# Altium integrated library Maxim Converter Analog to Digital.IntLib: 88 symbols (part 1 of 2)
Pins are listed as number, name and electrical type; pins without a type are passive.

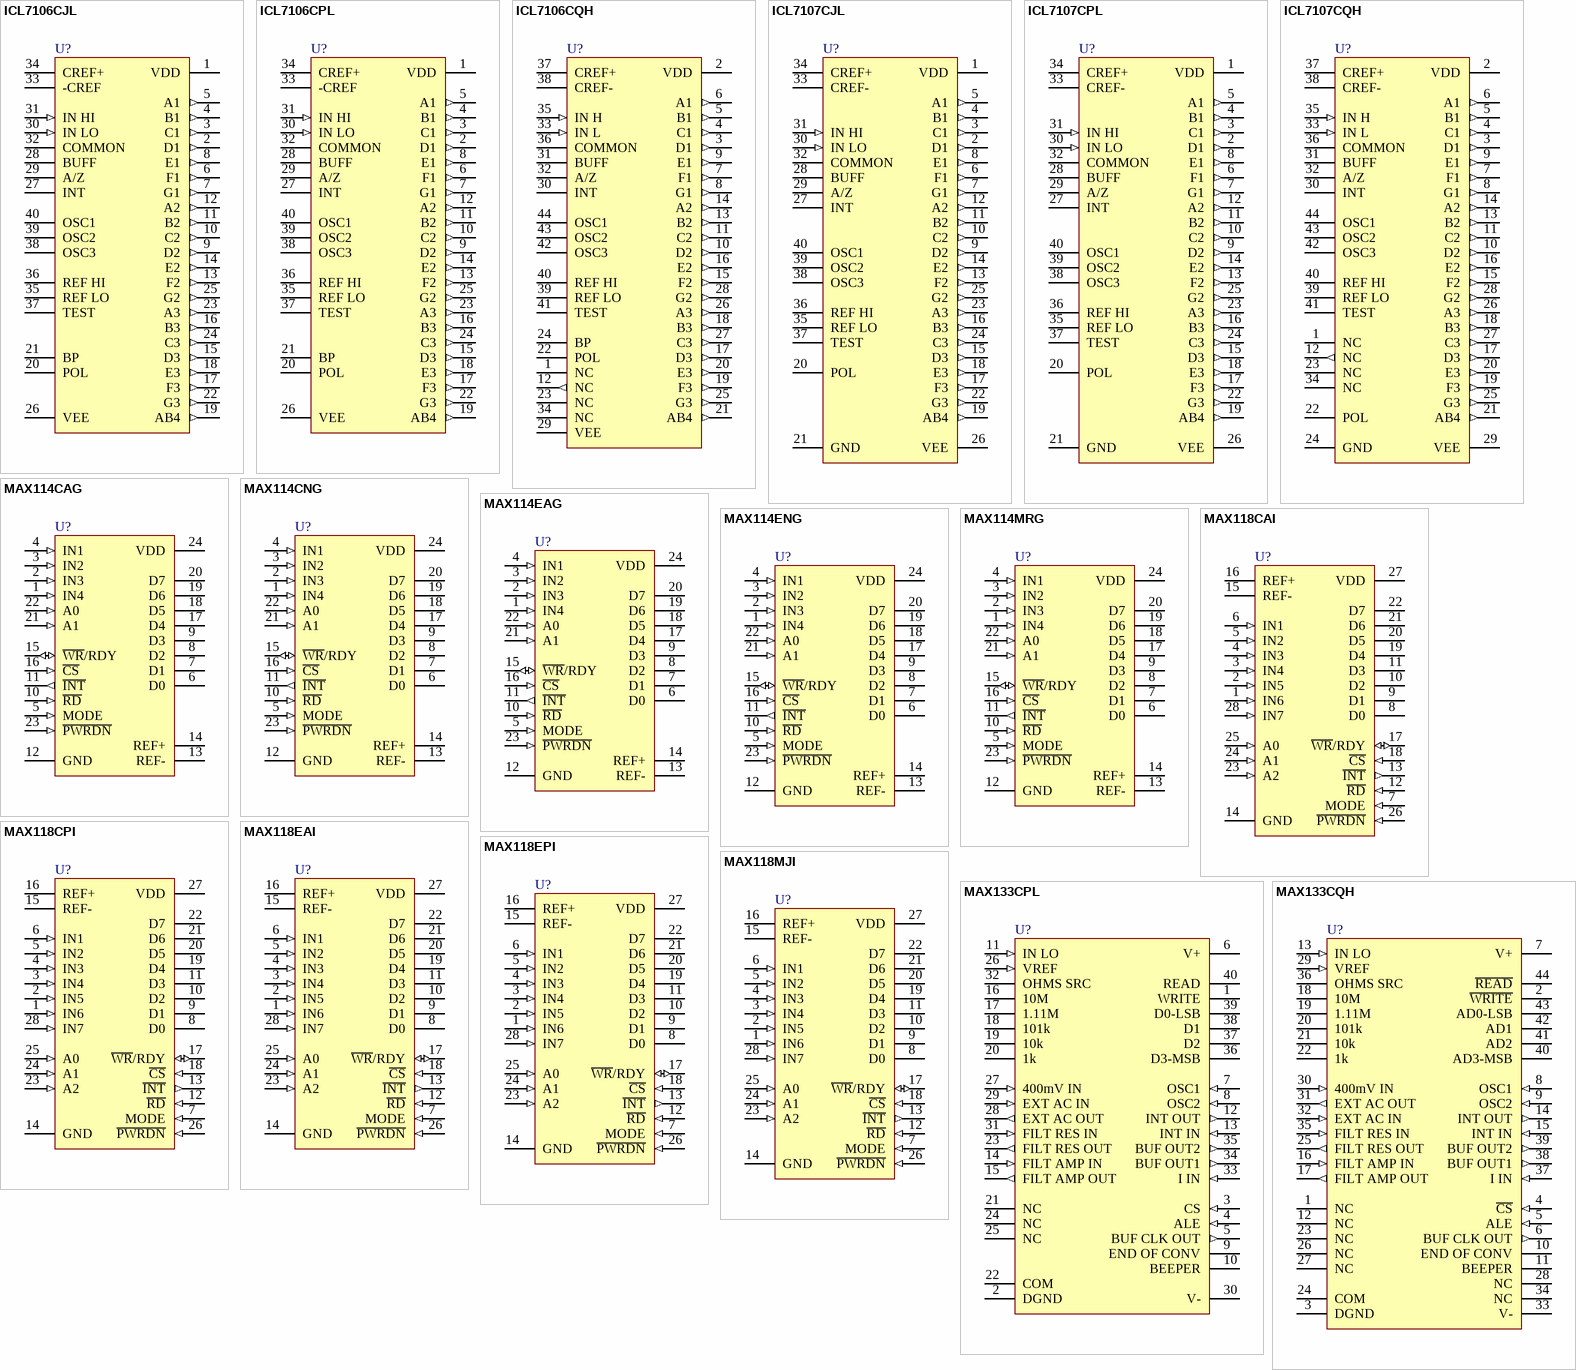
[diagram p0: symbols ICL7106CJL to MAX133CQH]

## ICL7106CJL
designator U?
3½ Digit A/D Converter
footprint JL40A (DIP, 40-Leads, Row Spacing 15.24mm, Pitch 2.54mm, Body 52.28x14.35mm)
3D model JL40A (DIP, 40-Pin, Row Spacing 15.24 mm, Pitch 2.54 mm)
pins: 1 VDD (power), 2 D1 (out), 3 C1 (out), 4 B1 (out), 5 A1 (out), 6 F1 (out), 7 G1 (out), 8 E1 (out), 9 D2 (out), 10 C2 (out), 11 B2 (out), 12 A2 (out), 13 F2 (out), 14 E2 (out), 15 D3 (out), 16 B3 (out), 17 F3 (out), 18 E3 (out), 19 AB4 (out), 20 POL, 21 BP, 22 G3 (out), 23 A3 (out), 24 C3 (out), 25 G2 (out), 26 VEE (power), 27 INT, 28 BUFF, 29 A/Z, 30 IN LO (in), 31 IN HI (in), 32 COMMON, 33 -CREF, 34 CREF+, 35 REF LO, 36 REF HI, 37 TEST, 38 OSC3, 39 OSC2, 40 OSC1

## ICL7106CPL
designator U?
3½ Digit A/D Converter
footprint PL40 (DIP, 40-Leads, Row Spacing 15.24mm, Pitch 2.54mm, Body 52.08x13.98mm)
3D model PL40 (DIP, 40-Pin, Row Spacing 15.24 mm, Pitch 2.54 mm)
pins: 1 VDD (power), 2 D1 (out), 3 C1 (out), 4 B1 (out), 5 A1 (out), 6 F1 (out), 7 G1 (out), 8 E1 (out), 9 D2 (out), 10 C2 (out), 11 B2 (out), 12 A2 (out), 13 F2 (out), 14 E2 (out), 15 D3 (out), 16 B3 (out), 17 F3 (out), 18 E3 (out), 19 AB4 (out), 20 POL, 21 BP, 22 G3 (out), 23 A3 (out), 24 C3 (out), 25 G2 (out), 26 VEE (power), 27 INT, 28 BUFF, 29 A/Z, 30 IN LO (in), 31 IN HI (in), 32 COMMON, 33 -CREF, 34 CREF+, 35 REF LO, 36 REF HI, 37 TEST, 38 OSC3, 39 OSC2, 40 OSC1

## ICL7106CQH
designator U?
3½ Digit A/D Converter
footprint PLCC44_N (Leaded Chip Carrier, 44-Leads, Body 16.6x16.6mm, Pitch 1.27mm, IPC Medium Density)
footprint PLCC44_L (Leaded Chip Carrier, 44-Leads, Body 16.6x16.6mm, Pitch 1.27mm, IPC High Density)
footprint PLCC44_M (Leaded Chip Carrier, 44-Leads, Body 16.6x16.6mm, Pitch 1.27mm, IPC Low Density)
3D model ICL7106-PLCC44 (44-Pin Leaded Chip Carrier 1.27 mm Pitch)
pins: 1 NC, 2 VDD (power), 3 D1 (out), 4 C1 (out), 5 B1 (out), 6 A1 (out), 7 F1 (out), 8 G1 (out), 9 E1 (out), 10 D2 (out), 11 C2 (out), 12 NC (out), 13 B2 (out), 14 A2 (out), 15 F2 (out), 16 E2 (out), 17 D3 (out), 18 B3 (out), 19 F3 (out), 20 E3 (out), 21 AB4 (out), 22 POL, 23 NC, 24 BP, 25 G3 (out), 26 A3 (out), 27 C3 (out), 28 G2 (out), 29 VEE (power), 30 INT, 31 BUFF, 32 A/Z, 33 IN L (in), 34 NC, 35 IN H (in), 36 COMMON, 37 CREF+, 38 CREF-, 39 REF LO, 40 REF HI, 41 TEST, 42 OSC3, 43 OSC2, 44 OSC1

## ICL7107CJL
designator U?
3½ Digit A/D Converter
footprint JL40A (DIP, 40-Leads, Row Spacing 15.24mm, Pitch 2.54mm, Body 52.28x14.35mm)
3D model JL40A (DIP, 40-Pin, Row Spacing 15.24 mm, Pitch 2.54 mm)
pins: 1 VDD (power), 2 D1 (out), 3 C1 (out), 4 B1 (out), 5 A1 (out), 6 F1 (out), 7 G1 (out), 8 E1 (out), 9 D2 (out), 10 C2 (out), 11 B2 (out), 12 A2 (out), 13 F2 (out), 14 E2 (out), 15 D3 (out), 16 B3 (out), 17 F3 (out), 18 E3 (out), 19 AB4 (out), 20 POL, 21 GND (power), 22 G3 (out), 23 A3 (out), 24 C3 (out), 25 G2 (out), 26 VEE (power), 27 INT, 28 BUFF, 29 A/Z, 30 IN LO (in), 31 IN HI (in), 32 COMMON, 33 CREF-, 34 CREF+, 35 REF LO, 36 REF HI, 37 TEST, 38 OSC3, 39 OSC2, 40 OSC1

## ICL7107CPL
designator U?
3½ Digit A/D Converter
footprint PL40 (DIP, 40-Leads, Row Spacing 15.24mm, Pitch 2.54mm, Body 52.08x13.98mm)
3D model PL40 (DIP, 40-Pin, Row Spacing 15.24 mm, Pitch 2.54 mm)
pins: 1 VDD (power), 2 D1 (out), 3 C1 (out), 4 B1 (out), 5 A1 (out), 6 F1 (out), 7 G1 (out), 8 E1 (out), 9 D2 (out), 10 C2 (out), 11 B2 (out), 12 A2 (out), 13 F2 (out), 14 E2 (out), 15 D3 (out), 16 B3 (out), 17 F3 (out), 18 E3 (out), 19 AB4 (out), 20 POL, 21 GND (power), 22 G3 (out), 23 A3 (out), 24 C3 (out), 25 G2 (out), 26 VEE (power), 27 INT, 28 BUFF, 29 A/Z, 30 IN LO (in), 31 IN HI (in), 32 COMMON, 33 CREF-, 34 CREF+, 35 REF LO, 36 REF HI, 37 TEST, 38 OSC3, 39 OSC2, 40 OSC1

## ICL7107CQH
designator U?
3½ Digit A/D Converter
footprint PLCC44_N (Leaded Chip Carrier, 44-Leads, Body 16.6x16.6mm, Pitch 1.27mm, IPC Medium Density)
footprint PLCC44_L (Leaded Chip Carrier, 44-Leads, Body 16.6x16.6mm, Pitch 1.27mm, IPC High Density)
footprint PLCC44_M (Leaded Chip Carrier, 44-Leads, Body 16.6x16.6mm, Pitch 1.27mm, IPC Low Density)
3D model ICL7107-PLCC44 (44-Pin Leaded Chip Carrier 1.27 mm Pitch)
pins: 1 NC, 2 VDD (power), 3 D1 (out), 4 C1 (out), 5 B1 (out), 6 A1 (out), 7 F1 (out), 8 G1 (out), 9 E1 (out), 10 D2 (out), 11 C2 (out), 12 NC (out), 13 B2 (out), 14 A2 (out), 15 F2 (out), 16 E2 (out), 17 D3 (out), 18 B3 (out), 19 F3 (out), 20 E3 (out), 21 AB4 (out), 22 POL, 23 NC, 24 GND (power), 25 G3 (out), 26 A3 (out), 27 C3 (out), 28 G2 (out), 29 VEE (power), 30 INT, 31 BUFF, 32 A/Z, 33 IN L (in), 34 NC, 35 IN H (in), 36 COMMON, 37 CREF+, 38 CREF-, 39 REF LO, 40 REF HI, 41 TEST, 42 OSC3, 43 OSC2, 44 OSC1

## MAX114CAG
designator U?
+5V, 1Msps, 4-Channel, 8-Bit ADCs with 1µA Power-Down
footprint SSOP24_N (SOP, 24-Leads, Body 8.2x5.3mm, Pitch 0.65mm, IPC Medium Density)
footprint SSOP24_L (SOP, 24-Leads, Body 8.2x5.3mm, Pitch 0.65mm, IPC High Density)
footprint SSOP24_M (SOP, 24-Leads, Body 8.2x5.3mm, Pitch 0.65mm, IPC Low Density)
3D model SSOP24 (24-Pin Small Outline Package 0.65 mm Pitch)
pins: 1 IN4 (in), 2 IN3 (in), 3 IN2 (in), 4 IN1 (in), 5 MODE (in), 6 D0 (hiz), 7 D1 (hiz), 8 D2 (hiz), 9 D3 (hiz), 10 ~{RD} (in), 11 ~{INT} (out), 12 GND (power), 13 REF-, 14 REF+, 15 ~{WR}/RDY (io), 16 ~{CS} (in), 17 D4 (hiz), 18 D5 (hiz), 19 D6 (hiz), 20 D7 (hiz), 21 A1 (in), 22 A0 (in), 23 ~{PWRDN} (in), 24 VDD (power)

## MAX114CNG
designator U?
+5V, 1Msps, 4-Channel, 8-Bit ADCs with 1µA Power-Down
footprint NG24 (DIP, 24-Leads, Row Spacing 7.62mm, Pitch 2.54mm, Body 30.55x7.24mm)
3D model NG24 (DIP, 24-Pin, Row Spacing 7.62 mm, Pitch 2.54 mm)
pins: 1 IN4 (in), 2 IN3 (in), 3 IN2 (in), 4 IN1 (in), 5 MODE (in), 6 D0 (hiz), 7 D1 (hiz), 8 D2 (hiz), 9 D3 (hiz), 10 ~{RD} (in), 11 ~{INT} (out), 12 GND (power), 13 REF-, 14 REF+, 15 ~{WR}/RDY (io), 16 ~{CS} (in), 17 D4 (hiz), 18 D5 (hiz), 19 D6 (hiz), 20 D7 (hiz), 21 A1 (in), 22 A0 (in), 23 ~{PWRDN} (in), 24 VDD (power)

## MAX114EAG
designator U?
+5V, 1Msps, 4-Channel, 8-Bit ADCs with 1µA Power-Down
footprint SSOP24_N (SOP, 24-Leads, Body 8.2x5.3mm, Pitch 0.65mm, IPC Medium Density)
footprint SSOP24_L (SOP, 24-Leads, Body 8.2x5.3mm, Pitch 0.65mm, IPC High Density)
footprint SSOP24_M (SOP, 24-Leads, Body 8.2x5.3mm, Pitch 0.65mm, IPC Low Density)
3D model SSOP24 (24-Pin Small Outline Package 0.65 mm Pitch)
pins: 1 IN4 (in), 2 IN3 (in), 3 IN2 (in), 4 IN1 (in), 5 MODE (in), 6 D0 (hiz), 7 D1 (hiz), 8 D2 (hiz), 9 D3 (hiz), 10 ~{RD} (in), 11 ~{INT} (out), 12 GND (power), 13 REF-, 14 REF+, 15 ~{WR}/RDY (io), 16 ~{CS} (in), 17 D4 (hiz), 18 D5 (hiz), 19 D6 (hiz), 20 D7 (hiz), 21 A1 (in), 22 A0 (in), 23 ~{PWRDN} (in), 24 VDD (power)

## MAX114ENG
designator U?
+5V, 1Msps, 4-Channel, 8-Bit ADCs with 1µA Power-Down
footprint NG24 (DIP, 24-Leads, Row Spacing 7.62mm, Pitch 2.54mm, Body 30.55x7.24mm)
3D model NG24 (DIP, 24-Pin, Row Spacing 7.62 mm, Pitch 2.54 mm)
pins: 1 IN4 (in), 2 IN3 (in), 3 IN2 (in), 4 IN1 (in), 5 MODE (in), 6 D0 (hiz), 7 D1 (hiz), 8 D2 (hiz), 9 D3 (hiz), 10 ~{RD} (in), 11 ~{INT} (out), 12 GND (power), 13 REF-, 14 REF+, 15 ~{WR}/RDY (io), 16 ~{CS} (in), 17 D4 (hiz), 18 D5 (hiz), 19 D6 (hiz), 20 D7 (hiz), 21 A1 (in), 22 A0 (in), 23 ~{PWRDN} (in), 24 VDD (power)

## MAX114MRG
designator U?
+5V, 1Msps, 4-Channel, 8-Bit ADCs with 1µA Power-Down
footprint RG24 (DIP, 24-Leads, Row Spacing 7.62mm, Pitch 2.54mm, Body 31.88x6.73mm)
3D model NG24 (DIP, 24-Pin, Row Spacing 7.62 mm, Pitch 2.54 mm)
pins: 1 IN4 (in), 2 IN3 (in), 3 IN2 (in), 4 IN1 (in), 5 MODE (in), 6 D0 (hiz), 7 D1 (hiz), 8 D2 (hiz), 9 D3 (hiz), 10 ~{RD} (in), 11 ~{INT} (out), 12 GND (power), 13 REF-, 14 REF+, 15 ~{WR}/RDY (io), 16 ~{CS} (in), 17 D4 (hiz), 18 D5 (hiz), 19 D6 (hiz), 20 D7 (hiz), 21 A1 (in), 22 A0 (in), 23 ~{PWRDN} (in), 24 VDD (power)

## MAX118CAI
designator U?
+5V, 1Msps, 8-Channel, 8-Bit ADCs with 1µA Power-Down
footprint SSOP28_N (SOP, 28-Leads, Body 10.2x5.3mm, Pitch 0.65mm, IPC Medium Density)
footprint SSOP28_L (SOP, 28-Leads, Body 10.2x5.3mm, Pitch 0.65mm, IPC High Density)
footprint SSOP28_M (SOP, 28-Leads, Body 10.2x5.3mm, Pitch 0.65mm, IPC Low Density)
3D model SSOP28 (28-Pin Small Outline Package 0.65 mm Pitch)
pins: 1 IN6 (in), 2 IN5 (in), 3 IN4 (in), 4 IN3 (in), 5 IN2 (in), 6 IN1 (in), 7 MODE (in), 8 D0 (hiz), 9 D1 (hiz), 10 D2 (hiz), 11 D3 (hiz), 12 ~{RD} (in), 13 ~{INT} (out), 14 GND (power), 15 REF-, 16 REF+, 17 ~{WR}/RDY (io), 18 ~{CS} (in), 19 D4 (hiz), 20 D5 (hiz), 21 D6 (hiz), 22 D7 (hiz), 23 A2 (in), 24 A1 (in), 25 A0 (in), 26 ~{PWRDN} (in), 27 VDD (power), 28 IN7 (in)

## MAX118CPI
designator U?
+5V, 1Msps, 8-Channel, 8-Bit ADCs with 1µA Power-Down
footprint PI28 (DIP, 28-Leads, Row Spacing 15.24mm, Pitch 2.54mm, Body 36.83x13.98mm)
3D model JI28 (DIP, 28-Pin, Row Spacing 15.24 mm, Pitch 2.54 mm)
pins: 1 IN6 (in), 2 IN5 (in), 3 IN4 (in), 4 IN3 (in), 5 IN2 (in), 6 IN1 (in), 7 MODE (in), 8 D0 (hiz), 9 D1 (hiz), 10 D2 (hiz), 11 D3 (hiz), 12 ~{RD} (in), 13 ~{INT} (out), 14 GND (power), 15 REF-, 16 REF+, 17 ~{WR}/RDY (io), 18 ~{CS} (in), 19 D4 (hiz), 20 D5 (hiz), 21 D6 (hiz), 22 D7 (hiz), 23 A2 (in), 24 A1 (in), 25 A0 (in), 26 ~{PWRDN} (in), 27 VDD (power), 28 IN7 (in)

## MAX118EAI
designator U?
+5V, 1Msps, 8-Channel, 8-Bit ADCs with 1µA Power-Down
footprint SSOP28_N (SOP, 28-Leads, Body 10.2x5.3mm, Pitch 0.65mm, IPC Medium Density)
footprint SSOP28_L (SOP, 28-Leads, Body 10.2x5.3mm, Pitch 0.65mm, IPC High Density)
footprint SSOP28_M (SOP, 28-Leads, Body 10.2x5.3mm, Pitch 0.65mm, IPC Low Density)
3D model SSOP28 (28-Pin Small Outline Package 0.65 mm Pitch)
pins: 1 IN6 (in), 2 IN5 (in), 3 IN4 (in), 4 IN3 (in), 5 IN2 (in), 6 IN1 (in), 7 MODE (in), 8 D0 (hiz), 9 D1 (hiz), 10 D2 (hiz), 11 D3 (hiz), 12 ~{RD} (in), 13 ~{INT} (out), 14 GND (power), 15 REF-, 16 REF+, 17 ~{WR}/RDY (io), 18 ~{CS} (in), 19 D4 (hiz), 20 D5 (hiz), 21 D6 (hiz), 22 D7 (hiz), 23 A2 (in), 24 A1 (in), 25 A0 (in), 26 ~{PWRDN} (in), 27 VDD (power), 28 IN7 (in)

## MAX118EPI
designator U?
+5V, 1Msps, 8-Channel, 8-Bit ADCs with 1µA Power-Down
footprint PI28 (DIP, 28-Leads, Row Spacing 15.24mm, Pitch 2.54mm, Body 36.83x13.98mm)
3D model JI28 (DIP, 28-Pin, Row Spacing 15.24 mm, Pitch 2.54 mm)
pins: 1 IN6 (in), 2 IN5 (in), 3 IN4 (in), 4 IN3 (in), 5 IN2 (in), 6 IN1 (in), 7 MODE (in), 8 D0 (hiz), 9 D1 (hiz), 10 D2 (hiz), 11 D3 (hiz), 12 ~{RD} (in), 13 ~{INT} (out), 14 GND (power), 15 REF-, 16 REF+, 17 ~{WR}/RDY (io), 18 ~{CS} (in), 19 D4 (hiz), 20 D5 (hiz), 21 D6 (hiz), 22 D7 (hiz), 23 A2 (in), 24 A1 (in), 25 A0 (in), 26 ~{PWRDN} (in), 27 VDD (power), 28 IN7 (in)

## MAX118MJI
designator U?
+5V, 1Msps, 8-Channel, 8-Bit ADCs with 1µA Power-Down
footprint JI28 (DIP, 28-Leads, Row Spacing 15.24mm, Pitch 2.54mm, Body 37.15x14.23mm)
3D model JI28 (DIP, 28-Pin, Row Spacing 15.24 mm, Pitch 2.54 mm)
pins: 1 IN6 (in), 2 IN5 (in), 3 IN4 (in), 4 IN3 (in), 5 IN2 (in), 6 IN1 (in), 7 MODE (in), 8 D0 (hiz), 9 D1 (hiz), 10 D2 (hiz), 11 D3 (hiz), 12 ~{RD} (in), 13 ~{INT} (out), 14 GND (power), 15 REF-, 16 REF+, 17 ~{WR}/RDY (io), 18 ~{CS} (in), 19 D4 (hiz), 20 D5 (hiz), 21 D6 (hiz), 22 D7 (hiz), 23 A2 (in), 24 A1 (in), 25 A0 (in), 26 ~{PWRDN} (in), 27 VDD (power), 28 IN7 (in)

## MAX133CPL
designator U?
3¾ Digit DMM Circuit
footprint PL40 (DIP, 40-Leads, Row Spacing 15.24mm, Pitch 2.54mm, Body 52.08x13.98mm)
3D model PL40 (DIP, 40-Pin, Row Spacing 15.24 mm, Pitch 2.54 mm)
pins: 1 WRITE, 2 DGND (power), 3 CS (in), 4 ALE (in), 5 BUF CLK OUT (out), 6 V+ (power), 7 OSC1 (in), 8 OSC2 (in), 9 END OF CONV, 10 BEEPER, 11 IN LO (in), 12 INT OUT (out), 13 INT IN (in), 14 FILT AMP IN (in), 15 FILT AMP OUT (out), 16 10M, 17 1.11M, 18 101k, 19 10k, 20 1k, 21 NC, 22 COM (power), 23 FILT RES OUT (out), 24 NC, 25 NC, 26 VREF (in), 27 400mV IN (in), 28 EXT AC OUT (out), 29 EXT AC IN (in), 30 V- (power), 31 FILT RES IN (in), 32 OHMS SRC, 33 I IN (in), 34 BUF OUT1 (out), 35 BUF OUT2 (out), 36 D3-MSB, 37 D2, 38 D1, 39 D0-LSB, 40 READ

## MAX133CQH
designator U?
3¾ Digit DMM Circuit
footprint PLCC44_N (Leaded Chip Carrier, 44-Leads, Body 16.6x16.6mm, Pitch 1.27mm, IPC Medium Density)
footprint PLCC44_L (Leaded Chip Carrier, 44-Leads, Body 16.6x16.6mm, Pitch 1.27mm, IPC High Density)
footprint PLCC44_M (Leaded Chip Carrier, 44-Leads, Body 16.6x16.6mm, Pitch 1.27mm, IPC Low Density)
3D model MAX133-PLCC44 (44-Pin Leaded Chip Carrier 1.27 mm Pitch)
pins: 1 NC, 2 ~{WRITE}, 3 DGND (power), 4 ~{CS} (in), 5 ALE (in), 6 BUF CLK OUT (out), 7 V+ (power), 8 OSC1 (in), 9 OSC2 (in), 10 END OF CONV, 11 BEEPER, 12 NC, 13 IN LO (in), 14 INT OUT (out), 15 INT IN (in), 16 FILT AMP IN (in), 17 FILT AMP OUT (out), 18 10M, 19 1.11M, 20 101k, 21 10k, 22 1k, 23 NC, 24 COM (power), 25 FILT RES OUT (out), 26 NC, 27 NC, 28 NC, 29 VREF (in), 30 400mV IN (in), 31 EXT AC OUT (out), 32 EXT AC IN (in), 33 V- (power), 34 NC, 35 FILT RES IN (in), 36 OHMS SRC, 37 I IN (in), 38 BUF OUT1 (out), 39 BUF OUT2 (out), 40 AD3-MSB, 41 AD2, 42 AD1, 43 AD0-LSB, 44 ~{READ}

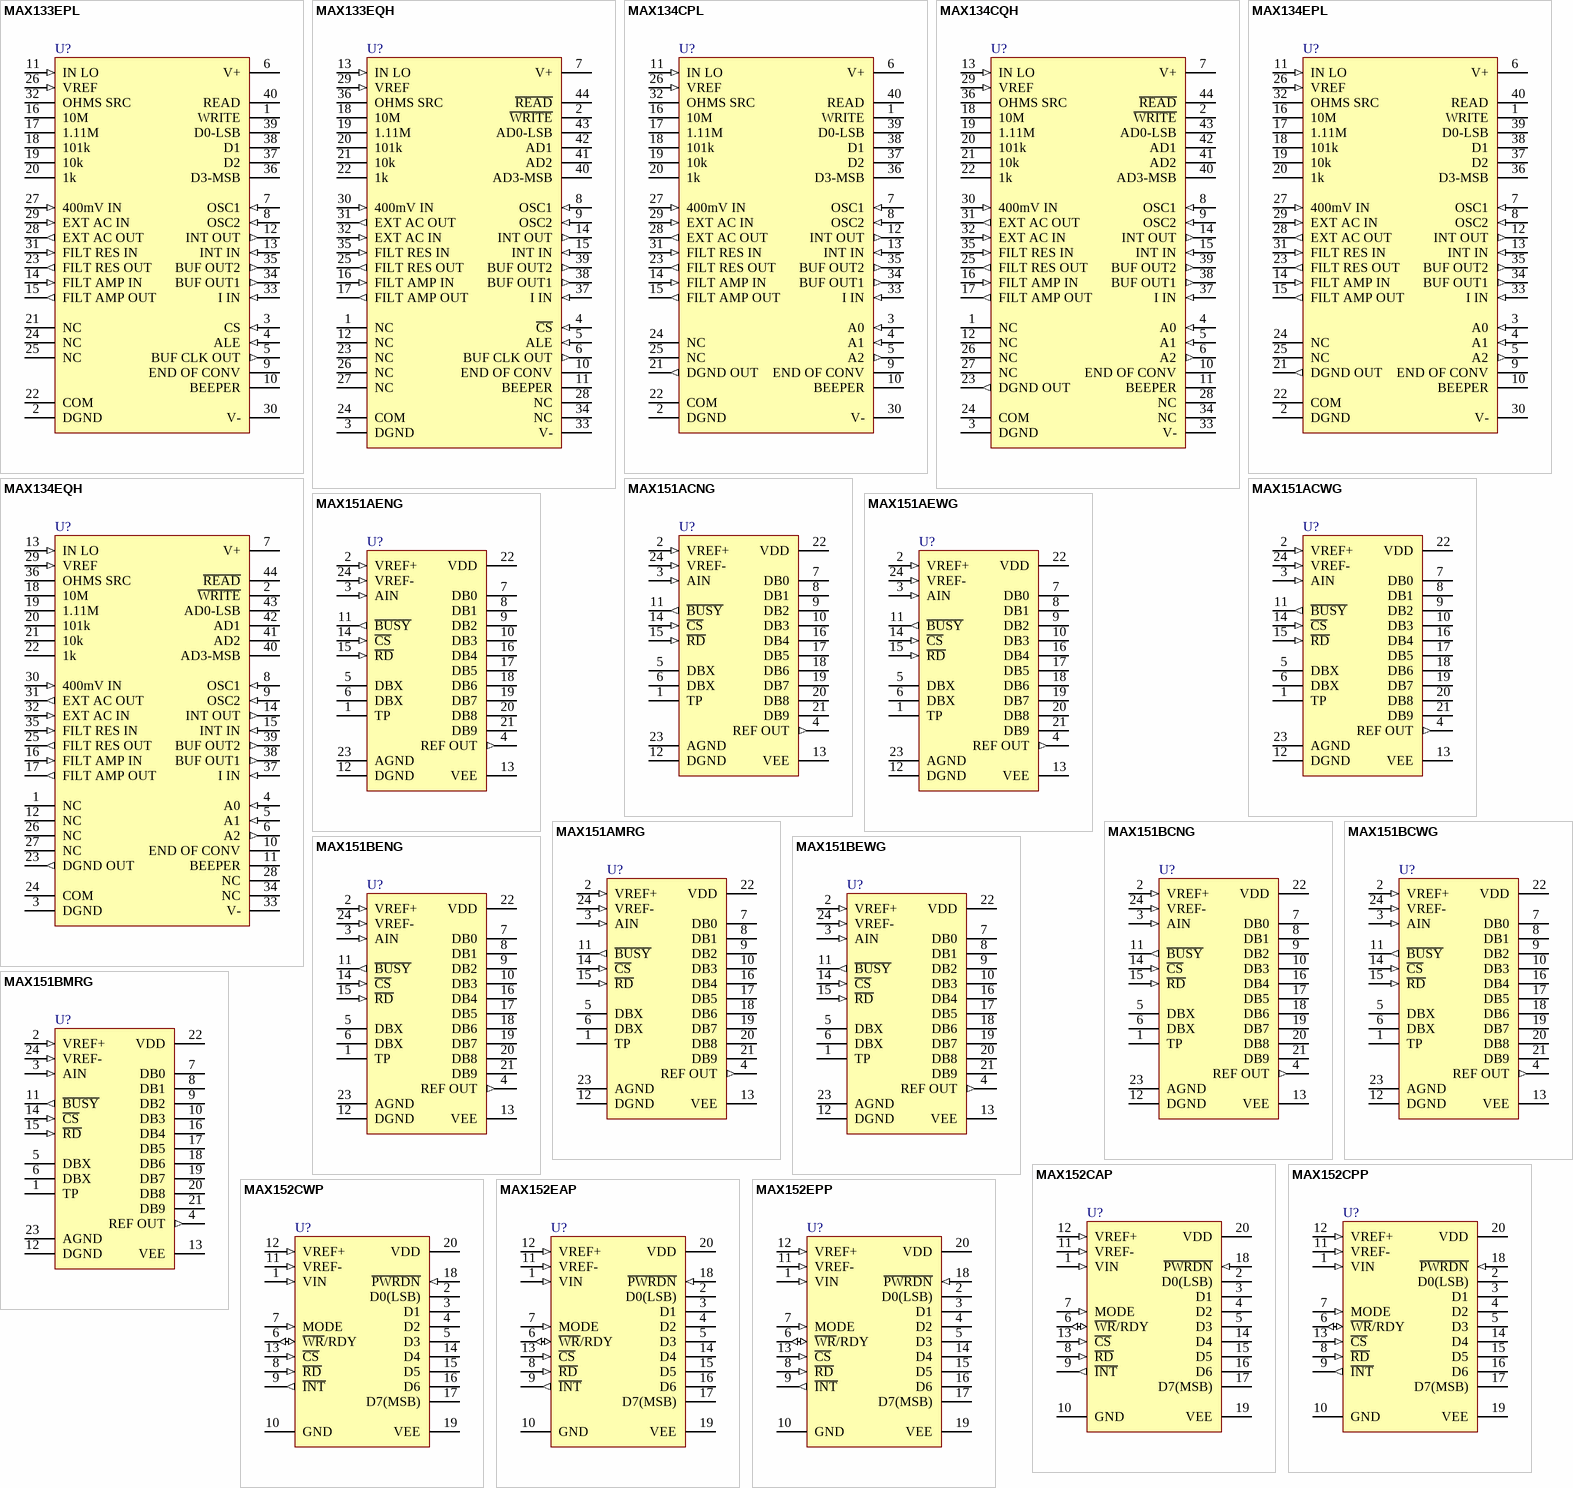
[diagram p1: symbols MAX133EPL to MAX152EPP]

## MAX133EPL
designator U?
3¾ Digit DMM Circuit
footprint PL40 (DIP, 40-Leads, Row Spacing 15.24mm, Pitch 2.54mm, Body 52.08x13.98mm)
3D model PL40 (DIP, 40-Pin, Row Spacing 15.24 mm, Pitch 2.54 mm)
pins: 1 WRITE, 2 DGND (power), 3 CS (in), 4 ALE (in), 5 BUF CLK OUT (out), 6 V+ (power), 7 OSC1 (in), 8 OSC2 (in), 9 END OF CONV, 10 BEEPER, 11 IN LO (in), 12 INT OUT (out), 13 INT IN (in), 14 FILT AMP IN (in), 15 FILT AMP OUT (out), 16 10M, 17 1.11M, 18 101k, 19 10k, 20 1k, 21 NC, 22 COM (power), 23 FILT RES OUT (out), 24 NC, 25 NC, 26 VREF (in), 27 400mV IN (in), 28 EXT AC OUT (out), 29 EXT AC IN (in), 30 V- (power), 31 FILT RES IN (in), 32 OHMS SRC, 33 I IN (in), 34 BUF OUT1 (out), 35 BUF OUT2 (out), 36 D3-MSB, 37 D2, 38 D1, 39 D0-LSB, 40 READ

## MAX133EQH
designator U?
3¾ Digit DMM Circuit
footprint PLCC44_N (Leaded Chip Carrier, 44-Leads, Body 16.6x16.6mm, Pitch 1.27mm, IPC Medium Density)
footprint PLCC44_L (Leaded Chip Carrier, 44-Leads, Body 16.6x16.6mm, Pitch 1.27mm, IPC High Density)
footprint PLCC44_M (Leaded Chip Carrier, 44-Leads, Body 16.6x16.6mm, Pitch 1.27mm, IPC Low Density)
3D model MAX133-PLCC44 (44-Pin Leaded Chip Carrier 1.27 mm Pitch)
pins: 1 NC, 2 ~{WRITE}, 3 DGND (power), 4 ~{CS} (in), 5 ALE (in), 6 BUF CLK OUT (out), 7 V+ (power), 8 OSC1 (in), 9 OSC2 (in), 10 END OF CONV, 11 BEEPER, 12 NC, 13 IN LO (in), 14 INT OUT (out), 15 INT IN (in), 16 FILT AMP IN (in), 17 FILT AMP OUT (out), 18 10M, 19 1.11M, 20 101k, 21 10k, 22 1k, 23 NC, 24 COM (power), 25 FILT RES OUT (out), 26 NC, 27 NC, 28 NC, 29 VREF (in), 30 400mV IN (in), 31 EXT AC OUT (out), 32 EXT AC IN (in), 33 V- (power), 34 NC, 35 FILT RES IN (in), 36 OHMS SRC, 37 I IN (in), 38 BUF OUT1 (out), 39 BUF OUT2 (out), 40 AD3-MSB, 41 AD2, 42 AD1, 43 AD0-LSB, 44 ~{READ}

## MAX134CPL
designator U?
3¾ Digit DMM Circuit
footprint PL40 (DIP, 40-Leads, Row Spacing 15.24mm, Pitch 2.54mm, Body 52.08x13.98mm)
3D model PL40 (DIP, 40-Pin, Row Spacing 15.24 mm, Pitch 2.54 mm)
pins: 1 WRITE, 2 DGND (power), 3 A0 (in), 4 A1 (in), 5 A2 (out), 6 V+ (power), 7 OSC1 (in), 8 OSC2 (in), 9 END OF CONV, 10 BEEPER, 11 IN LO (in), 12 INT OUT (out), 13 INT IN (in), 14 FILT AMP IN (in), 15 FILT AMP OUT (out), 16 10M, 17 1.11M, 18 101k, 19 10k, 20 1k, 21 DGND OUT (out), 22 COM (power), 23 FILT RES OUT (out), 24 NC, 25 NC, 26 VREF (in), 27 400mV IN (in), 28 EXT AC OUT (out), 29 EXT AC IN (in), 30 V- (power), 31 FILT RES IN (in), 32 OHMS SRC, 33 I IN (in), 34 BUF OUT1 (out), 35 BUF OUT2 (out), 36 D3-MSB, 37 D2, 38 D1, 39 D0-LSB, 40 READ

## MAX134CQH
designator U?
3¾ Digit DMM Circuit
footprint PLCC44_N (Leaded Chip Carrier, 44-Leads, Body 16.6x16.6mm, Pitch 1.27mm, IPC Medium Density)
footprint PLCC44_L (Leaded Chip Carrier, 44-Leads, Body 16.6x16.6mm, Pitch 1.27mm, IPC High Density)
footprint PLCC44_M (Leaded Chip Carrier, 44-Leads, Body 16.6x16.6mm, Pitch 1.27mm, IPC Low Density)
3D model MAX134-PLCC44 (44-Pin Leaded Chip Carrier 1.27 mm Pitch)
pins: 1 NC, 2 ~{WRITE}, 3 DGND (power), 4 A0 (in), 5 A1 (in), 6 A2 (out), 7 V+ (power), 8 OSC1 (in), 9 OSC2 (in), 10 END OF CONV, 11 BEEPER, 12 NC, 13 IN LO (in), 14 INT OUT (out), 15 INT IN (in), 16 FILT AMP IN (in), 17 FILT AMP OUT (out), 18 10M, 19 1.11M, 20 101k, 21 10k, 22 1k, 23 DGND OUT (out), 24 COM (power), 25 FILT RES OUT (out), 26 NC, 27 NC, 28 NC, 29 VREF (in), 30 400mV IN (in), 31 EXT AC OUT (out), 32 EXT AC IN (in), 33 V- (power), 34 NC, 35 FILT RES IN (in), 36 OHMS SRC, 37 I IN (in), 38 BUF OUT1 (out), 39 BUF OUT2 (out), 40 AD3-MSB, 41 AD2, 42 AD1, 43 AD0-LSB, 44 ~{READ}

## MAX134EPL
designator U?
3¾ Digit DMM Circuit
footprint PL40 (DIP, 40-Leads, Row Spacing 15.24mm, Pitch 2.54mm, Body 52.08x13.98mm)
3D model PL40 (DIP, 40-Pin, Row Spacing 15.24 mm, Pitch 2.54 mm)
pins: 1 WRITE, 2 DGND (power), 3 A0 (in), 4 A1 (in), 5 A2 (out), 6 V+ (power), 7 OSC1 (in), 8 OSC2 (in), 9 END OF CONV, 10 BEEPER, 11 IN LO (in), 12 INT OUT (out), 13 INT IN (in), 14 FILT AMP IN (in), 15 FILT AMP OUT (out), 16 10M, 17 1.11M, 18 101k, 19 10k, 20 1k, 21 DGND OUT (out), 22 COM (power), 23 FILT RES OUT (out), 24 NC, 25 NC, 26 VREF (in), 27 400mV IN (in), 28 EXT AC OUT (out), 29 EXT AC IN (in), 30 V- (power), 31 FILT RES IN (in), 32 OHMS SRC, 33 I IN (in), 34 BUF OUT1 (out), 35 BUF OUT2 (out), 36 D3-MSB, 37 D2, 38 D1, 39 D0-LSB, 40 READ

## MAX134EQH
designator U?
3¾ Digit DMM Circuit
footprint PLCC44_N (Leaded Chip Carrier, 44-Leads, Body 16.6x16.6mm, Pitch 1.27mm, IPC Medium Density)
footprint PLCC44_L (Leaded Chip Carrier, 44-Leads, Body 16.6x16.6mm, Pitch 1.27mm, IPC High Density)
footprint PLCC44_M (Leaded Chip Carrier, 44-Leads, Body 16.6x16.6mm, Pitch 1.27mm, IPC Low Density)
3D model MAX134-PLCC44 (44-Pin Leaded Chip Carrier 1.27 mm Pitch)
pins: 1 NC, 2 ~{WRITE}, 3 DGND (power), 4 A0 (in), 5 A1 (in), 6 A2 (out), 7 V+ (power), 8 OSC1 (in), 9 OSC2 (in), 10 END OF CONV, 11 BEEPER, 12 NC, 13 IN LO (in), 14 INT OUT (out), 15 INT IN (in), 16 FILT AMP IN (in), 17 FILT AMP OUT (out), 18 10M, 19 1.11M, 20 101k, 21 10k, 22 1k, 23 DGND OUT (out), 24 COM (power), 25 FILT RES OUT (out), 26 NC, 27 NC, 28 NC, 29 VREF (in), 30 400mV IN (in), 31 EXT AC OUT (out), 32 EXT AC IN (in), 33 V- (power), 34 NC, 35 FILT RES IN (in), 36 OHMS SRC, 37 I IN (in), 38 BUF OUT1 (out), 39 BUF OUT2 (out), 40 AD3-MSB, 41 AD2, 42 AD1, 43 AD0-LSB, 44 ~{READ}

## MAX151ACNG
designator U?
300kHz 10-Bit ADC Converter with Reference and T/H
footprint NG24A (DIP, 24-Leads, Row Spacing 7.62mm, Pitch 2.54mm, Body 30.55x6.99mm)
3D model NG24 (DIP, 24-Pin, Row Spacing 7.62 mm, Pitch 2.54 mm)
pins: 1 TP, 2 VREF+ (in), 3 AIN (in), 4 REF OUT (out), 5 DBX, 6 DBX, 7 DB0 (hiz), 8 DB1 (hiz), 9 DB2 (hiz), 10 DB3 (hiz), 11 ~{BUSY} (out), 12 DGND (power), 13 VEE (power), 14 ~{CS} (in), 15 ~{RD} (in), 16 DB4 (hiz), 17 DB5 (hiz), 18 DB6 (hiz), 19 DB7 (hiz), 20 DB8 (hiz), 21 DB9 (hiz), 22 VDD (power), 23 AGND (power), 24 VREF- (in)

## MAX151ACWG
designator U?
300kHz 10-Bit ADC Converter with Reference and T/H
footprint WSO24_N (SOIC, 24-Leads, Body 15.4x7.5mm, Pitch 1.27mm, IPC Medium Density)
footprint WSO24_L (SOIC, 24-Leads, Body 15.4x7.5mm, Pitch 1.27mm, IPC High Density)
footprint WSO24_M (SOIC, 24-Leads, Body 15.4x7.5mm, Pitch 1.27mm, IPC Low Density)
3D model WSO24 (24-Pin Small Outline Integrated Circuit 1.27 mm Pitch)
pins: 1 TP, 2 VREF+ (in), 3 AIN (in), 4 REF OUT (out), 5 DBX, 6 DBX, 7 DB0 (hiz), 8 DB1 (hiz), 9 DB2 (hiz), 10 DB3 (hiz), 11 ~{BUSY} (out), 12 DGND (power), 13 VEE (power), 14 ~{CS} (in), 15 ~{RD} (in), 16 DB4 (hiz), 17 DB5 (hiz), 18 DB6 (hiz), 19 DB7 (hiz), 20 DB8 (hiz), 21 DB9 (hiz), 22 VDD (power), 23 AGND (power), 24 VREF- (in)

## MAX151AENG
designator U?
300kHz 10-Bit ADC Converter with Reference and T/H
footprint NG24A (DIP, 24-Leads, Row Spacing 7.62mm, Pitch 2.54mm, Body 30.55x6.99mm)
3D model NG24 (DIP, 24-Pin, Row Spacing 7.62 mm, Pitch 2.54 mm)
pins: 1 TP, 2 VREF+ (in), 3 AIN (in), 4 REF OUT (out), 5 DBX, 6 DBX, 7 DB0 (hiz), 8 DB1 (hiz), 9 DB2 (hiz), 10 DB3 (hiz), 11 ~{BUSY} (out), 12 DGND (power), 13 VEE (power), 14 ~{CS} (in), 15 ~{RD} (in), 16 DB4 (hiz), 17 DB5 (hiz), 18 DB6 (hiz), 19 DB7 (hiz), 20 DB8 (hiz), 21 DB9 (hiz), 22 VDD (power), 23 AGND (power), 24 VREF- (in)

## MAX151AEWG
designator U?
300kHz 10-Bit ADC Converter with Reference and T/H
footprint WSO24_N (SOIC, 24-Leads, Body 15.4x7.5mm, Pitch 1.27mm, IPC Medium Density)
footprint WSO24_L (SOIC, 24-Leads, Body 15.4x7.5mm, Pitch 1.27mm, IPC High Density)
footprint WSO24_M (SOIC, 24-Leads, Body 15.4x7.5mm, Pitch 1.27mm, IPC Low Density)
3D model WSO24 (24-Pin Small Outline Integrated Circuit 1.27 mm Pitch)
pins: 1 TP, 2 VREF+ (in), 3 AIN (in), 4 REF OUT (out), 5 DBX, 6 DBX, 7 DB0 (hiz), 8 DB1 (hiz), 9 DB2 (hiz), 10 DB3 (hiz), 11 ~{BUSY} (out), 12 DGND (power), 13 VEE (power), 14 ~{CS} (in), 15 ~{RD} (in), 16 DB4 (hiz), 17 DB5 (hiz), 18 DB6 (hiz), 19 DB7 (hiz), 20 DB8 (hiz), 21 DB9 (hiz), 22 VDD (power), 23 AGND (power), 24 VREF- (in)

## MAX151AMRG
designator U?
300kHz 10-Bit ADC Converter with Reference and T/H
footprint RG24 (DIP, 24-Leads, Row Spacing 7.62mm, Pitch 2.54mm, Body 31.88x6.73mm)
3D model NG24 (DIP, 24-Pin, Row Spacing 7.62 mm, Pitch 2.54 mm)
pins: 1 TP, 2 VREF+ (in), 3 AIN (in), 4 REF OUT (out), 5 DBX, 6 DBX, 7 DB0 (hiz), 8 DB1 (hiz), 9 DB2 (hiz), 10 DB3 (hiz), 11 ~{BUSY} (out), 12 DGND (power), 13 VEE (power), 14 ~{CS} (in), 15 ~{RD} (in), 16 DB4 (hiz), 17 DB5 (hiz), 18 DB6 (hiz), 19 DB7 (hiz), 20 DB8 (hiz), 21 DB9 (hiz), 22 VDD (power), 23 AGND (power), 24 VREF- (in)

## MAX151BCNG
designator U?
300kHz 10-Bit ADC Converter with Reference and T/H
footprint NG24A (DIP, 24-Leads, Row Spacing 7.62mm, Pitch 2.54mm, Body 30.55x6.99mm)
3D model NG24 (DIP, 24-Pin, Row Spacing 7.62 mm, Pitch 2.54 mm)
pins: 1 TP, 2 VREF+ (in), 3 AIN (in), 4 REF OUT (out), 5 DBX, 6 DBX, 7 DB0 (hiz), 8 DB1 (hiz), 9 DB2 (hiz), 10 DB3 (hiz), 11 ~{BUSY} (out), 12 DGND (power), 13 VEE (power), 14 ~{CS} (in), 15 ~{RD} (in), 16 DB4 (hiz), 17 DB5 (hiz), 18 DB6 (hiz), 19 DB7 (hiz), 20 DB8 (hiz), 21 DB9 (hiz), 22 VDD (power), 23 AGND (power), 24 VREF- (in)

## MAX151BCWG
designator U?
300kHz 10-Bit ADC Converter with Reference and T/H
footprint WSO24_N (SOIC, 24-Leads, Body 15.4x7.5mm, Pitch 1.27mm, IPC Medium Density)
footprint WSO24_L (SOIC, 24-Leads, Body 15.4x7.5mm, Pitch 1.27mm, IPC High Density)
footprint WSO24_M (SOIC, 24-Leads, Body 15.4x7.5mm, Pitch 1.27mm, IPC Low Density)
3D model WSO24 (24-Pin Small Outline Integrated Circuit 1.27 mm Pitch)
pins: 1 TP, 2 VREF+ (in), 3 AIN (in), 4 REF OUT (out), 5 DBX, 6 DBX, 7 DB0 (hiz), 8 DB1 (hiz), 9 DB2 (hiz), 10 DB3 (hiz), 11 ~{BUSY} (out), 12 DGND (power), 13 VEE (power), 14 ~{CS} (in), 15 ~{RD} (in), 16 DB4 (hiz), 17 DB5 (hiz), 18 DB6 (hiz), 19 DB7 (hiz), 20 DB8 (hiz), 21 DB9 (hiz), 22 VDD (power), 23 AGND (power), 24 VREF- (in)

## MAX151BENG
designator U?
300kHz 10-Bit ADC Converter with Reference and T/H
footprint NG24A (DIP, 24-Leads, Row Spacing 7.62mm, Pitch 2.54mm, Body 30.55x6.99mm)
3D model NG24 (DIP, 24-Pin, Row Spacing 7.62 mm, Pitch 2.54 mm)
pins: 1 TP, 2 VREF+ (in), 3 AIN (in), 4 REF OUT (out), 5 DBX, 6 DBX, 7 DB0 (hiz), 8 DB1 (hiz), 9 DB2 (hiz), 10 DB3 (hiz), 11 ~{BUSY} (out), 12 DGND (power), 13 VEE (power), 14 ~{CS} (in), 15 ~{RD} (in), 16 DB4 (hiz), 17 DB5 (hiz), 18 DB6 (hiz), 19 DB7 (hiz), 20 DB8 (hiz), 21 DB9 (hiz), 22 VDD (power), 23 AGND (power), 24 VREF- (in)

## MAX151BEWG
designator U?
300kHz 10-Bit ADC Converter with Reference and T/H
footprint WSO24_N (SOIC, 24-Leads, Body 15.4x7.5mm, Pitch 1.27mm, IPC Medium Density)
footprint WSO24_L (SOIC, 24-Leads, Body 15.4x7.5mm, Pitch 1.27mm, IPC High Density)
footprint WSO24_M (SOIC, 24-Leads, Body 15.4x7.5mm, Pitch 1.27mm, IPC Low Density)
3D model WSO24 (24-Pin Small Outline Integrated Circuit 1.27 mm Pitch)
pins: 1 TP, 2 VREF+ (in), 3 AIN (in), 4 REF OUT (out), 5 DBX, 6 DBX, 7 DB0 (hiz), 8 DB1 (hiz), 9 DB2 (hiz), 10 DB3 (hiz), 11 ~{BUSY} (out), 12 DGND (power), 13 VEE (power), 14 ~{CS} (in), 15 ~{RD} (in), 16 DB4 (hiz), 17 DB5 (hiz), 18 DB6 (hiz), 19 DB7 (hiz), 20 DB8 (hiz), 21 DB9 (hiz), 22 VDD (power), 23 AGND (power), 24 VREF- (in)

## MAX151BMRG
designator U?
300kHz 10-Bit ADC Converter with Reference and T/H
footprint RG24 (DIP, 24-Leads, Row Spacing 7.62mm, Pitch 2.54mm, Body 31.88x6.73mm)
3D model NG24 (DIP, 24-Pin, Row Spacing 7.62 mm, Pitch 2.54 mm)
pins: 1 TP, 2 VREF+ (in), 3 AIN (in), 4 REF OUT (out), 5 DBX, 6 DBX, 7 DB0 (hiz), 8 DB1 (hiz), 9 DB2 (hiz), 10 DB3 (hiz), 11 ~{BUSY} (out), 12 DGND (power), 13 VEE (power), 14 ~{CS} (in), 15 ~{RD} (in), 16 DB4 (hiz), 17 DB5 (hiz), 18 DB6 (hiz), 19 DB7 (hiz), 20 DB8 (hiz), 21 DB9 (hiz), 22 VDD (power), 23 AGND (power), 24 VREF- (in)

## MAX152CAP
designator U?
3V+, 8-Bit ADC with 1µA Power-Down
footprint PSOP20_N (SOIC, 20-Leads, Body 12.8x7.5mm, Pitch 1.27mm, IPC Medium Density)
footprint PSOP20_L (SOIC, 20-Leads, Body 12.8x7.5mm, Pitch 1.27mm, IPC High Density)
footprint PSOP20_M (SOIC, 20-Leads, Body 12.8x7.5mm, Pitch 1.27mm, IPC Low Density)
3D model WSO20 (20-Pin Small Outline Integrated Circuit 1.27 mm Pitch)
pins: 1 VIN (in), 2 D0(LSB) (hiz), 3 D1 (hiz), 4 D2 (hiz), 5 D3 (hiz), 6 ~{WR}/RDY (io), 7 MODE (in), 8 ~{RD} (in), 9 ~{INT} (out), 10 GND (power), 11 VREF- (in), 12 VREF+ (in), 13 ~{CS} (in), 14 D4 (hiz), 15 D5 (hiz), 16 D6 (hiz), 17 D7(MSB) (hiz), 18 ~{PWRDN} (in), 19 VEE (power), 20 VDD (power)

## MAX152CPP
designator U?
3V+, 8-Bit ADC with 1µA Power-Down
footprint PP20 (DIP, 20-Leads, Row Spacing 7.62mm, Pitch 2.54mm, Body 26.16x7.24mm)
3D model PP20 (DIP, 20-Pin, Row Spacing 7.62 mm, Pitch 2.54 mm)
pins: 1 VIN (in), 2 D0(LSB) (hiz), 3 D1 (hiz), 4 D2 (hiz), 5 D3 (hiz), 6 ~{WR}/RDY (io), 7 MODE (in), 8 ~{RD} (in), 9 ~{INT} (out), 10 GND (power), 11 VREF- (in), 12 VREF+ (in), 13 ~{CS} (in), 14 D4 (hiz), 15 D5 (hiz), 16 D6 (hiz), 17 D7(MSB) (hiz), 18 ~{PWRDN} (in), 19 VEE (power), 20 VDD (power)

## MAX152CWP
designator U?
3V+, 8-Bit ADC with 1µA Power-Down
footprint WSO20_N (SOIC, 20-Leads, Body 12.8x7.5mm, Pitch 1.27mm, IPC Medium Density)
footprint WSO20_L (SOIC, 20-Leads, Body 12.8x7.5mm, Pitch 1.27mm, IPC High Density)
footprint WSO20_M (SOIC, 20-Leads, Body 12.8x7.5mm, Pitch 1.27mm, IPC Low Density)
3D model WSO20 (20-Pin Small Outline Integrated Circuit 1.27 mm Pitch)
pins: 1 VIN (in), 2 D0(LSB) (hiz), 3 D1 (hiz), 4 D2 (hiz), 5 D3 (hiz), 6 ~{WR}/RDY (io), 7 MODE (in), 8 ~{RD} (in), 9 ~{INT} (out), 10 GND (power), 11 VREF- (in), 12 VREF+ (in), 13 ~{CS} (in), 14 D4 (hiz), 15 D5 (hiz), 16 D6 (hiz), 17 D7(MSB) (hiz), 18 ~{PWRDN} (in), 19 VEE (power), 20 VDD (power)

## MAX152EAP
designator U?
3V+, 8-Bit ADC with 1µA Power-Down
footprint PSOP20_N (SOIC, 20-Leads, Body 12.8x7.5mm, Pitch 1.27mm, IPC Medium Density)
footprint PSOP20_L (SOIC, 20-Leads, Body 12.8x7.5mm, Pitch 1.27mm, IPC High Density)
footprint PSOP20_M (SOIC, 20-Leads, Body 12.8x7.5mm, Pitch 1.27mm, IPC Low Density)
3D model WSO20 (20-Pin Small Outline Integrated Circuit 1.27 mm Pitch)
pins: 1 VIN (in), 2 D0(LSB) (hiz), 3 D1 (hiz), 4 D2 (hiz), 5 D3 (hiz), 6 ~{WR}/RDY (io), 7 MODE (in), 8 ~{RD} (in), 9 ~{INT} (out), 10 GND (power), 11 VREF- (in), 12 VREF+ (in), 13 ~{CS} (in), 14 D4 (hiz), 15 D5 (hiz), 16 D6 (hiz), 17 D7(MSB) (hiz), 18 ~{PWRDN} (in), 19 VEE (power), 20 VDD (power)

## MAX152EPP
designator U?
3V+, 8-Bit ADC with 1µA Power-Down
footprint PP20 (DIP, 20-Leads, Row Spacing 7.62mm, Pitch 2.54mm, Body 26.16x7.24mm)
3D model PP20 (DIP, 20-Pin, Row Spacing 7.62 mm, Pitch 2.54 mm)
pins: 1 VIN (in), 2 D0(LSB) (hiz), 3 D1 (hiz), 4 D2 (hiz), 5 D3 (hiz), 6 ~{WR}/RDY (io), 7 MODE (in), 8 ~{RD} (in), 9 ~{INT} (out), 10 GND (power), 11 VREF- (in), 12 VREF+ (in), 13 ~{CS} (in), 14 D4 (hiz), 15 D5 (hiz), 16 D6 (hiz), 17 D7(MSB) (hiz), 18 ~{PWRDN} (in), 19 VEE (power), 20 VDD (power)

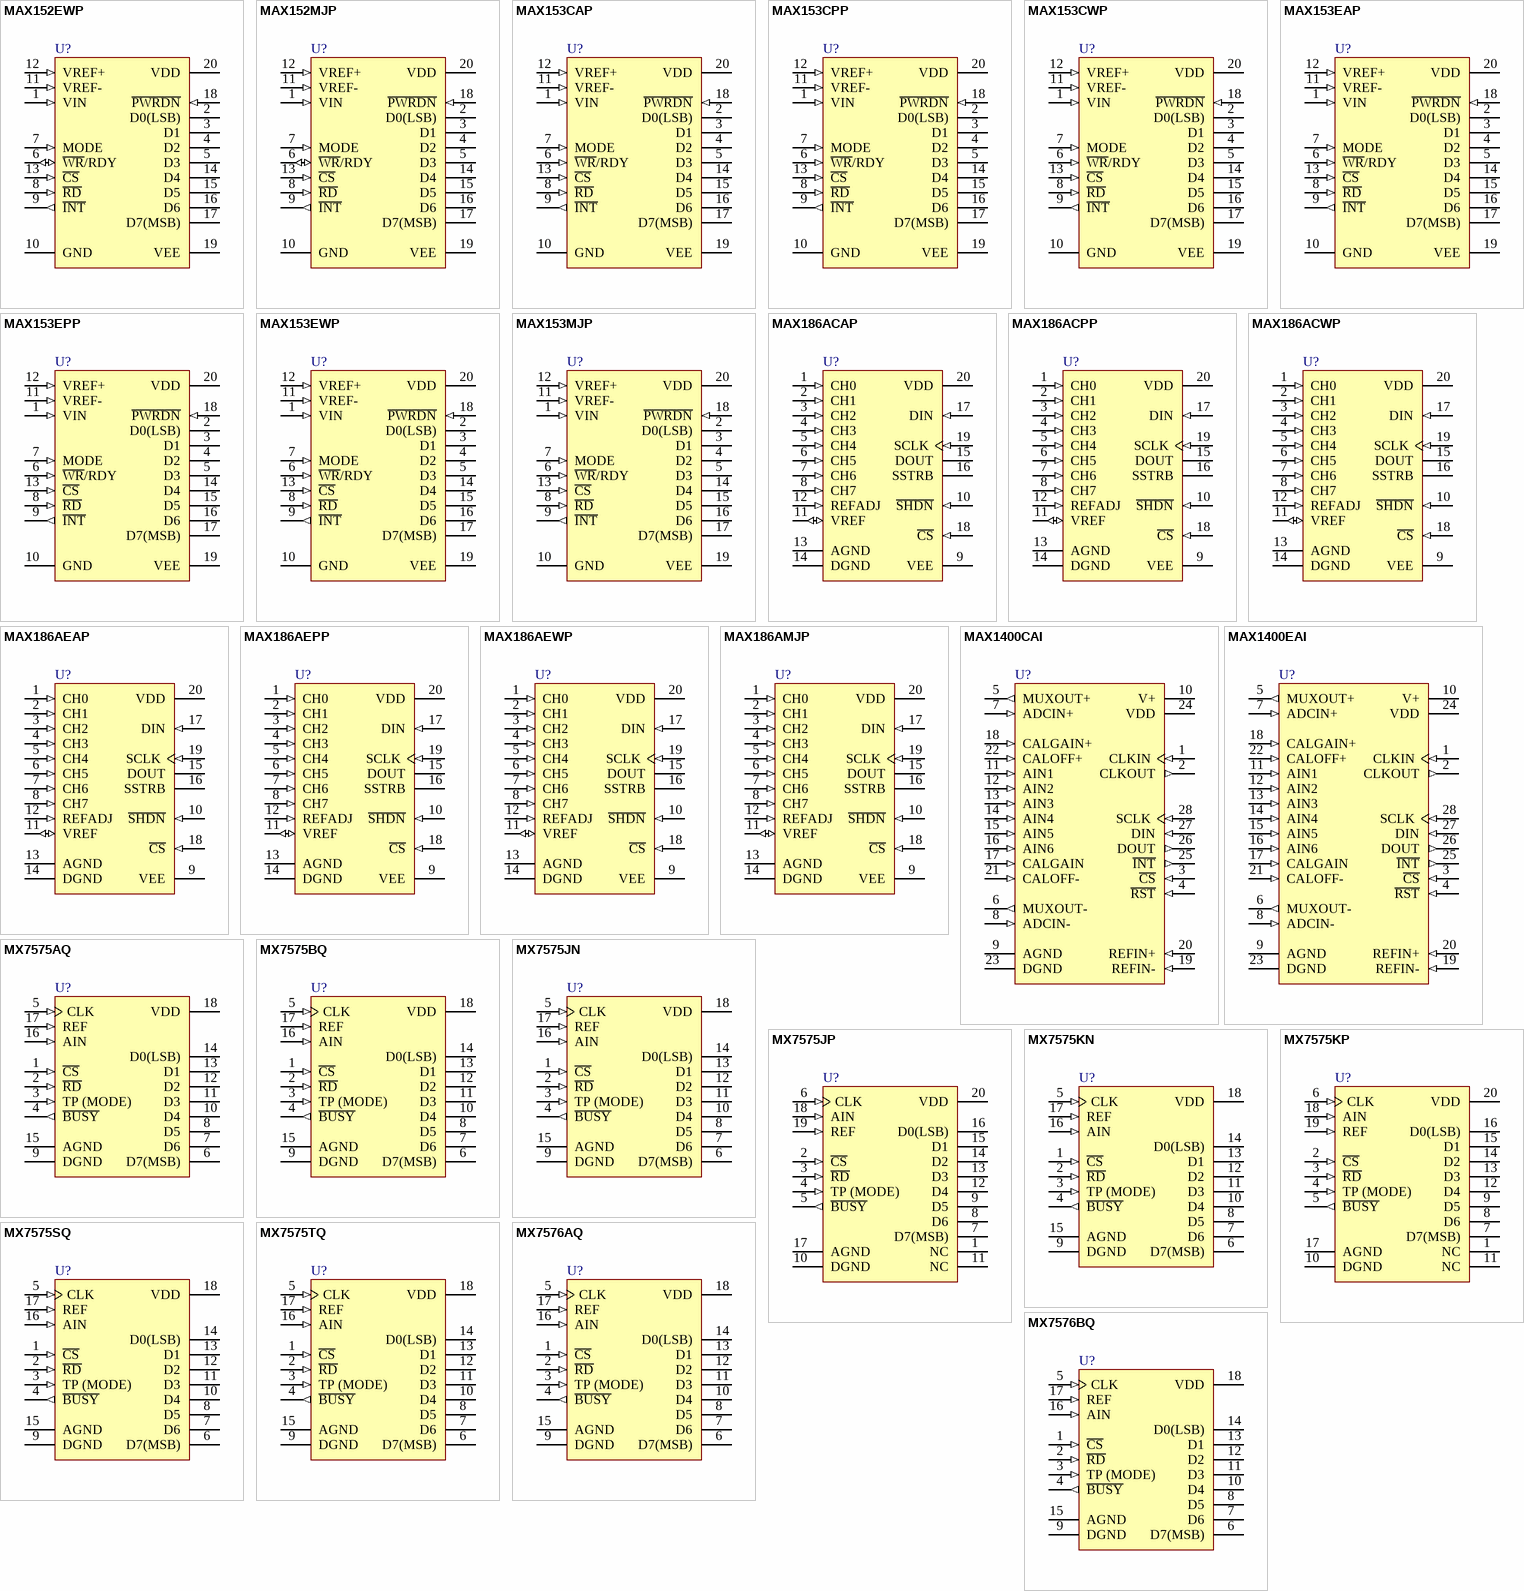
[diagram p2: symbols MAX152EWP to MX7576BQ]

## MAX152EWP
designator U?
3V+, 8-Bit ADC with 1µA Power-Down
footprint WSO20_N (SOIC, 20-Leads, Body 12.8x7.5mm, Pitch 1.27mm, IPC Medium Density)
footprint WSO20_L (SOIC, 20-Leads, Body 12.8x7.5mm, Pitch 1.27mm, IPC High Density)
footprint WSO20_M (SOIC, 20-Leads, Body 12.8x7.5mm, Pitch 1.27mm, IPC Low Density)
3D model WSO20 (20-Pin Small Outline Integrated Circuit 1.27 mm Pitch)
pins: 1 VIN (in), 2 D0(LSB) (hiz), 3 D1 (hiz), 4 D2 (hiz), 5 D3 (hiz), 6 ~{WR}/RDY (io), 7 MODE (in), 8 ~{RD} (in), 9 ~{INT} (out), 10 GND (power), 11 VREF- (in), 12 VREF+ (in), 13 ~{CS} (in), 14 D4 (hiz), 15 D5 (hiz), 16 D6 (hiz), 17 D7(MSB) (hiz), 18 ~{PWRDN} (in), 19 VEE (power), 20 VDD (power)

## MAX152MJP
designator U?
3V+, 8-Bit ADC with 1µA Power-Down
footprint JP20 (DIP, 20-Leads, Row Spacing 7.62mm, Pitch 2.54mm, Body 25.91x6.73mm)
3D model PP20 (DIP, 20-Pin, Row Spacing 7.62 mm, Pitch 2.54 mm)
pins: 1 VIN (in), 2 D0(LSB) (hiz), 3 D1 (hiz), 4 D2 (hiz), 5 D3 (hiz), 6 ~{WR}/RDY (io), 7 MODE (in), 8 ~{RD} (in), 9 ~{INT} (out), 10 GND (power), 11 VREF- (in), 12 VREF+ (in), 13 ~{CS} (in), 14 D4 (hiz), 15 D5 (hiz), 16 D6 (hiz), 17 D7(MSB) (hiz), 18 ~{PWRDN} (in), 19 VEE (power), 20 VDD (power)

## MAX153CAP
designator U?
1 Msps, µP-compatible, 8-Bit ADC with 1µA Power-Down
footprint SSOP20_N (SOP, 20-Leads, Body 7.2x5.3mm, Pitch 0.65mm, IPC Medium Density)
footprint SSOP20_L (SOP, 20-Leads, Body 7.2x5.3mm, Pitch 0.65mm, IPC High Density)
footprint SSOP20_M (SOP, 20-Leads, Body 7.2x5.3mm, Pitch 0.65mm, IPC Low Density)
3D model SSOP20 (20-Pin Small Outline Package 0.65 mm Pitch)
pins: 1 VIN (in), 2 D0(LSB) (hiz), 3 D1 (hiz), 4 D2 (hiz), 5 D3 (hiz), 6 ~{WR}/RDY (in), 7 MODE (in), 8 ~{RD} (in), 9 ~{INT} (out), 10 GND (power), 11 VREF- (in), 12 VREF+ (in), 13 ~{CS} (in), 14 D4 (hiz), 15 D5 (hiz), 16 D6 (hiz), 17 D7(MSB) (hiz), 18 ~{PWRDN} (in), 19 VEE (power), 20 VDD (power)

## MAX153CPP
designator U?
1 Msps, µP-compatible, 8-Bit ADC with 1µA Power-Down
footprint PP20 (DIP, 20-Leads, Row Spacing 7.62mm, Pitch 2.54mm, Body 26.16x7.24mm)
3D model PP20 (DIP, 20-Pin, Row Spacing 7.62 mm, Pitch 2.54 mm)
pins: 1 VIN (in), 2 D0(LSB) (hiz), 3 D1 (hiz), 4 D2 (hiz), 5 D3 (hiz), 6 ~{WR}/RDY (in), 7 MODE (in), 8 ~{RD} (in), 9 ~{INT} (out), 10 GND (power), 11 VREF- (in), 12 VREF+ (in), 13 ~{CS} (in), 14 D4 (hiz), 15 D5 (hiz), 16 D6 (hiz), 17 D7(MSB) (hiz), 18 ~{PWRDN} (in), 19 VEE (power), 20 VDD (power)

## MAX153CWP
designator U?
1 Msps, µP-compatible, 8-Bit ADC with 1µA Power-Down
footprint WSO20_N (SOIC, 20-Leads, Body 12.8x7.5mm, Pitch 1.27mm, IPC Medium Density)
footprint WSO20_L (SOIC, 20-Leads, Body 12.8x7.5mm, Pitch 1.27mm, IPC High Density)
footprint WSO20_M (SOIC, 20-Leads, Body 12.8x7.5mm, Pitch 1.27mm, IPC Low Density)
3D model WSO20 (20-Pin Small Outline Integrated Circuit 1.27 mm Pitch)
pins: 1 VIN (in), 2 D0(LSB) (hiz), 3 D1 (hiz), 4 D2 (hiz), 5 D3 (hiz), 6 ~{WR}/RDY (in), 7 MODE (in), 8 ~{RD} (in), 9 ~{INT} (out), 10 GND (power), 11 VREF- (in), 12 VREF+ (in), 13 ~{CS} (in), 14 D4 (hiz), 15 D5 (hiz), 16 D6 (hiz), 17 D7(MSB) (hiz), 18 ~{PWRDN} (in), 19 VEE (power), 20 VDD (power)

## MAX153EAP
designator U?
1 Msps, µP-compatible, 8-Bit ADC with 1µA Power-Down
footprint SSOP20_N (SOP, 20-Leads, Body 7.2x5.3mm, Pitch 0.65mm, IPC Medium Density)
footprint SSOP20_L (SOP, 20-Leads, Body 7.2x5.3mm, Pitch 0.65mm, IPC High Density)
footprint SSOP20_M (SOP, 20-Leads, Body 7.2x5.3mm, Pitch 0.65mm, IPC Low Density)
3D model SSOP20 (20-Pin Small Outline Package 0.65 mm Pitch)
pins: 1 VIN (in), 2 D0(LSB) (hiz), 3 D1 (hiz), 4 D2 (hiz), 5 D3 (hiz), 6 ~{WR}/RDY (in), 7 MODE (in), 8 ~{RD} (in), 9 ~{INT} (out), 10 GND (power), 11 VREF- (in), 12 VREF+ (in), 13 ~{CS} (in), 14 D4 (hiz), 15 D5 (hiz), 16 D6 (hiz), 17 D7(MSB) (hiz), 18 ~{PWRDN} (in), 19 VEE (power), 20 VDD (power)

## MAX153EPP
designator U?
1 Msps, µP-compatible, 8-Bit ADC with 1µA Power-Down
footprint PP20 (DIP, 20-Leads, Row Spacing 7.62mm, Pitch 2.54mm, Body 26.16x7.24mm)
3D model PP20 (DIP, 20-Pin, Row Spacing 7.62 mm, Pitch 2.54 mm)
pins: 1 VIN (in), 2 D0(LSB) (hiz), 3 D1 (hiz), 4 D2 (hiz), 5 D3 (hiz), 6 ~{WR}/RDY (in), 7 MODE (in), 8 ~{RD} (in), 9 ~{INT} (out), 10 GND (power), 11 VREF- (in), 12 VREF+ (in), 13 ~{CS} (in), 14 D4 (hiz), 15 D5 (hiz), 16 D6 (hiz), 17 D7(MSB) (hiz), 18 ~{PWRDN} (in), 19 VEE (power), 20 VDD (power)

## MAX153EWP
designator U?
1 Msps, µP-compatible, 8-Bit ADC with 1µA Power-Down
footprint WSO20_N (SOIC, 20-Leads, Body 12.8x7.5mm, Pitch 1.27mm, IPC Medium Density)
footprint WSO20_L (SOIC, 20-Leads, Body 12.8x7.5mm, Pitch 1.27mm, IPC High Density)
footprint WSO20_M (SOIC, 20-Leads, Body 12.8x7.5mm, Pitch 1.27mm, IPC Low Density)
3D model WSO20 (20-Pin Small Outline Integrated Circuit 1.27 mm Pitch)
pins: 1 VIN (in), 2 D0(LSB) (hiz), 3 D1 (hiz), 4 D2 (hiz), 5 D3 (hiz), 6 ~{WR}/RDY (in), 7 MODE (in), 8 ~{RD} (in), 9 ~{INT} (out), 10 GND (power), 11 VREF- (in), 12 VREF+ (in), 13 ~{CS} (in), 14 D4 (hiz), 15 D5 (hiz), 16 D6 (hiz), 17 D7(MSB) (hiz), 18 ~{PWRDN} (in), 19 VEE (power), 20 VDD (power)

## MAX153MJP
designator U?
1 Msps, µP-compatible, 8-Bit ADC with 1µA Power-Down
footprint JP20 (DIP, 20-Leads, Row Spacing 7.62mm, Pitch 2.54mm, Body 25.91x6.73mm)
3D model PP20 (DIP, 20-Pin, Row Spacing 7.62 mm, Pitch 2.54 mm)
pins: 1 VIN (in), 2 D0(LSB) (hiz), 3 D1 (hiz), 4 D2 (hiz), 5 D3 (hiz), 6 ~{WR}/RDY (in), 7 MODE (in), 8 ~{RD} (in), 9 ~{INT} (out), 10 GND (power), 11 VREF- (in), 12 VREF+ (in), 13 ~{CS} (in), 14 D4 (hiz), 15 D5 (hiz), 16 D6 (hiz), 17 D7(MSB) (hiz), 18 ~{PWRDN} (in), 19 VEE (power), 20 VDD (power)

## MAX186ACAP
designator U?
Low-Power, 8-Channel Serial 12-Bit ADCs
footprint SSOP20_N (SOP, 20-Leads, Body 7.2x5.3mm, Pitch 0.65mm, IPC Medium Density)
footprint SSOP20_L (SOP, 20-Leads, Body 7.2x5.3mm, Pitch 0.65mm, IPC High Density)
footprint SSOP20_M (SOP, 20-Leads, Body 7.2x5.3mm, Pitch 0.65mm, IPC Low Density)
3D model SSOP20 (20-Pin Small Outline Package 0.65 mm Pitch)
pins: 1 CH0 (in), 2 CH1 (in), 3 CH2 (in), 4 CH3 (in), 5 CH4 (in), 6 CH5 (in), 7 CH6 (in), 8 CH7 (in), 9 VEE (power), 10 ~{SHDN} (in), 11 VREF (io), 12 REFADJ (in), 13 AGND (power), 14 DGND (power), 15 DOUT (hiz), 16 SSTRB (hiz), 17 DIN (in), 18 ~{CS} (in), 19 SCLK (in), 20 VDD (power)

## MAX186ACPP
designator U?
Low-Power, 8-Channel Serial 12-Bit ADCs
footprint PP20 (DIP, 20-Leads, Row Spacing 7.62mm, Pitch 2.54mm, Body 26.16x7.24mm)
3D model PP20 (DIP, 20-Pin, Row Spacing 7.62 mm, Pitch 2.54 mm)
pins: 1 CH0 (in), 2 CH1 (in), 3 CH2 (in), 4 CH3 (in), 5 CH4 (in), 6 CH5 (in), 7 CH6 (in), 8 CH7 (in), 9 VEE (power), 10 ~{SHDN} (in), 11 VREF (io), 12 REFADJ (in), 13 AGND (power), 14 DGND (power), 15 DOUT (hiz), 16 SSTRB (hiz), 17 DIN (in), 18 ~{CS} (in), 19 SCLK (in), 20 VDD (power)

## MAX186ACWP
designator U?
Low-Power, 8-Channel Serial 12-Bit ADCs
footprint WSO20_N (SOIC, 20-Leads, Body 12.8x7.5mm, Pitch 1.27mm, IPC Medium Density)
footprint WSO20_L (SOIC, 20-Leads, Body 12.8x7.5mm, Pitch 1.27mm, IPC High Density)
footprint WSO20_M (SOIC, 20-Leads, Body 12.8x7.5mm, Pitch 1.27mm, IPC Low Density)
3D model WSO20 (20-Pin Small Outline Integrated Circuit 1.27 mm Pitch)
pins: 1 CH0 (in), 2 CH1 (in), 3 CH2 (in), 4 CH3 (in), 5 CH4 (in), 6 CH5 (in), 7 CH6 (in), 8 CH7 (in), 9 VEE (power), 10 ~{SHDN} (in), 11 VREF (io), 12 REFADJ (in), 13 AGND (power), 14 DGND (power), 15 DOUT (hiz), 16 SSTRB (hiz), 17 DIN (in), 18 ~{CS} (in), 19 SCLK (in), 20 VDD (power)

## MAX186AEAP
designator U?
Low-Power, 8-Channel Serial 12-Bit ADCs
footprint SSOP20_N (SOP, 20-Leads, Body 7.2x5.3mm, Pitch 0.65mm, IPC Medium Density)
footprint SSOP20_L (SOP, 20-Leads, Body 7.2x5.3mm, Pitch 0.65mm, IPC High Density)
footprint SSOP20_M (SOP, 20-Leads, Body 7.2x5.3mm, Pitch 0.65mm, IPC Low Density)
3D model SSOP20 (20-Pin Small Outline Package 0.65 mm Pitch)
pins: 1 CH0 (in), 2 CH1 (in), 3 CH2 (in), 4 CH3 (in), 5 CH4 (in), 6 CH5 (in), 7 CH6 (in), 8 CH7 (in), 9 VEE (power), 10 ~{SHDN} (in), 11 VREF (io), 12 REFADJ (in), 13 AGND (power), 14 DGND (power), 15 DOUT (hiz), 16 SSTRB (hiz), 17 DIN (in), 18 ~{CS} (in), 19 SCLK (in), 20 VDD (power)

## MAX186AEPP
designator U?
Low-Power, 8-Channel Serial 12-Bit ADCs
footprint PP20 (DIP, 20-Leads, Row Spacing 7.62mm, Pitch 2.54mm, Body 26.16x7.24mm)
3D model PP20 (DIP, 20-Pin, Row Spacing 7.62 mm, Pitch 2.54 mm)
pins: 1 CH0 (in), 2 CH1 (in), 3 CH2 (in), 4 CH3 (in), 5 CH4 (in), 6 CH5 (in), 7 CH6 (in), 8 CH7 (in), 9 VEE (power), 10 ~{SHDN} (in), 11 VREF (io), 12 REFADJ (in), 13 AGND (power), 14 DGND (power), 15 DOUT (hiz), 16 SSTRB (hiz), 17 DIN (in), 18 ~{CS} (in), 19 SCLK (in), 20 VDD (power)

## MAX186AEWP
designator U?
Low-Power, 8-Channel Serial 12-Bit ADCs
footprint WSO20_N (SOIC, 20-Leads, Body 12.8x7.5mm, Pitch 1.27mm, IPC Medium Density)
footprint WSO20_L (SOIC, 20-Leads, Body 12.8x7.5mm, Pitch 1.27mm, IPC High Density)
footprint WSO20_M (SOIC, 20-Leads, Body 12.8x7.5mm, Pitch 1.27mm, IPC Low Density)
3D model WSO20 (20-Pin Small Outline Integrated Circuit 1.27 mm Pitch)
pins: 1 CH0 (in), 2 CH1 (in), 3 CH2 (in), 4 CH3 (in), 5 CH4 (in), 6 CH5 (in), 7 CH6 (in), 8 CH7 (in), 9 VEE (power), 10 ~{SHDN} (in), 11 VREF (io), 12 REFADJ (in), 13 AGND (power), 14 DGND (power), 15 DOUT (hiz), 16 SSTRB (hiz), 17 DIN (in), 18 ~{CS} (in), 19 SCLK (in), 20 VDD (power)

## MAX186AMJP
designator U?
Low-Power, 8-Channel Serial 12-Bit ADCs
footprint JP20 (DIP, 20-Leads, Row Spacing 7.62mm, Pitch 2.54mm, Body 25.91x6.73mm)
3D model PP20 (DIP, 20-Pin, Row Spacing 7.62 mm, Pitch 2.54 mm)
pins: 1 CH0 (in), 2 CH1 (in), 3 CH2 (in), 4 CH3 (in), 5 CH4 (in), 6 CH5 (in), 7 CH6 (in), 8 CH7 (in), 9 VEE (power), 10 ~{SHDN} (in), 11 VREF (io), 12 REFADJ (in), 13 AGND (power), 14 DGND (power), 15 DOUT (hiz), 16 SSTRB (hiz), 17 DIN (in), 18 ~{CS} (in), 19 SCLK (in), 20 VDD (power)

## MAX1400CAI
designator U?
+5V, 18-Bit, Low-Power, Multichannel, Oversampling (Sigma-Delta) ADC
footprint SSOP28_N (SOP, 28-Leads, Body 10.2x5.3mm, Pitch 0.65mm, IPC Medium Density)
footprint SSOP28_L (SOP, 28-Leads, Body 10.2x5.3mm, Pitch 0.65mm, IPC High Density)
footprint SSOP28_M (SOP, 28-Leads, Body 10.2x5.3mm, Pitch 0.65mm, IPC Low Density)
3D model SSOP28 (28-Pin Small Outline Package 0.65 mm Pitch)
pins: 1 CLKIN (in), 2 CLKOUT (out), 3 ~{CS} (in), 4 ~{RST} (in), 5 MUXOUT+ (out), 6 MUXOUT- (out), 7 ADCIN+ (in), 8 ADCIN- (in), 9 AGND (power), 10 V+ (power), 11 AIN1 (in), 12 AIN2 (in), 13 AIN3 (in), 14 AIN4 (in), 15 AIN5 (in), 16 AIN6 (in), 17 CALGAIN (in), 18 CALGAIN+ (in), 19 REFIN- (in), 20 REFIN+ (in), 21 CALOFF- (in), 22 CALOFF+ (in), 23 DGND (power), 24 VDD (power), 25 ~{INT} (out), 26 DOUT (out), 27 DIN (in), 28 SCLK (in)

## MAX1400EAI
designator U?
+5V, 18-Bit, Low-Power, Multichannel, Oversampling (Sigma-Delta) ADC
footprint SSOP28_N (SOP, 28-Leads, Body 10.2x5.3mm, Pitch 0.65mm, IPC Medium Density)
footprint SSOP28_L (SOP, 28-Leads, Body 10.2x5.3mm, Pitch 0.65mm, IPC High Density)
footprint SSOP28_M (SOP, 28-Leads, Body 10.2x5.3mm, Pitch 0.65mm, IPC Low Density)
3D model SSOP28 (28-Pin Small Outline Package 0.65 mm Pitch)
pins: 1 CLKIN (in), 2 CLKOUT (out), 3 ~{CS} (in), 4 ~{RST} (in), 5 MUXOUT+ (out), 6 MUXOUT- (out), 7 ADCIN+ (in), 8 ADCIN- (in), 9 AGND (power), 10 V+ (power), 11 AIN1 (in), 12 AIN2 (in), 13 AIN3 (in), 14 AIN4 (in), 15 AIN5 (in), 16 AIN6 (in), 17 CALGAIN (in), 18 CALGAIN+ (in), 19 REFIN- (in), 20 REFIN+ (in), 21 CALOFF- (in), 22 CALOFF+ (in), 23 DGND (power), 24 VDD (power), 25 ~{INT} (out), 26 DOUT (out), 27 DIN (in), 28 SCLK (in)

## MX7575AQ
designator U?
CMOS, µP-Compatible, 5µs 8-Bit ADCs
footprint JN18 (DIP, 18-Leads, Row Spacing 7.62mm, Pitch 2.54mm, Body 24.13x6.73mm)
3D model JN18 (DIP, 18-Pin, Row Spacing 7.62 mm, Pitch 2.54 mm)
pins: 1 ~{CS} (in), 2 ~{RD} (in), 3 TP (MODE) (in), 4 ~{BUSY} (out), 5 CLK (in), 6 D7(MSB) (hiz), 7 D6 (hiz), 8 D5 (hiz), 9 DGND (power), 10 D4 (hiz), 11 D3 (hiz), 12 D2 (hiz), 13 D1 (hiz), 14 D0(LSB) (hiz), 15 AGND (power), 16 AIN (in), 17 REF (in), 18 VDD (power)

## MX7575BQ
designator U?
CMOS, µP-Compatible, 5µs 8-Bit ADCs
footprint JN18 (DIP, 18-Leads, Row Spacing 7.62mm, Pitch 2.54mm, Body 24.13x6.73mm)
3D model JN18 (DIP, 18-Pin, Row Spacing 7.62 mm, Pitch 2.54 mm)
pins: 1 ~{CS} (in), 2 ~{RD} (in), 3 TP (MODE) (in), 4 ~{BUSY} (out), 5 CLK (in), 6 D7(MSB) (hiz), 7 D6 (hiz), 8 D5 (hiz), 9 DGND (power), 10 D4 (hiz), 11 D3 (hiz), 12 D2 (hiz), 13 D1 (hiz), 14 D0(LSB) (hiz), 15 AGND (power), 16 AIN (in), 17 REF (in), 18 VDD (power)

## MX7575JN
designator U?
CMOS, µP-Compatible, 5µs 8-Bit ADCs
footprint PN18A (DIP, 18-Leads, Row Spacing 7.62mm, Pitch 2.54mm, Body 22.86x6.99mm)
3D model PN18 (DIP, 18-Pin, Row Spacing 7.62 mm, Pitch 2.54 mm)
pins: 1 ~{CS} (in), 2 ~{RD} (in), 3 TP (MODE) (in), 4 ~{BUSY} (out), 5 CLK (in), 6 D7(MSB) (hiz), 7 D6 (hiz), 8 D5 (hiz), 9 DGND (power), 10 D4 (hiz), 11 D3 (hiz), 12 D2 (hiz), 13 D1 (hiz), 14 D0(LSB) (hiz), 15 AGND (power), 16 AIN (in), 17 REF (in), 18 VDD (power)

## MX7575JP
designator U?
CMOS, µP-Compatible, 5µs 8-Bit ADCs
footprint PLCC20_N (Leaded Chip Carrier, 20-Leads, Body 9x9mm, Pitch 1.27mm, IPC Medium Density)
footprint PLCC20_L (Leaded Chip Carrier, 20-Leads, Body 9x9mm, Pitch 1.27mm, IPC High Density)
footprint PLCC20_M (Leaded Chip Carrier, 20-Leads, Body 9x9mm, Pitch 1.27mm, IPC Low Density)
3D model MX7575-PLCC20 (20-Pin Leaded Chip Carrier 1.27 mm Pitch)
pins: 1 NC, 2 ~{CS} (in), 3 ~{RD} (in), 4 TP (MODE) (in), 5 ~{BUSY} (out), 6 CLK (in), 7 D7(MSB) (hiz), 8 D6 (hiz), 9 D5 (hiz), 10 DGND (power), 11 NC, 12 D4 (hiz), 13 D3 (hiz), 14 D2 (hiz), 15 D1 (hiz), 16 D0(LSB) (hiz), 17 AGND (power), 18 AIN (in), 19 REF (in), 20 VDD (power)

## MX7575KN
designator U?
CMOS, µP-Compatible, 5µs 8-Bit ADCs
footprint PN18A (DIP, 18-Leads, Row Spacing 7.62mm, Pitch 2.54mm, Body 22.86x6.99mm)
3D model PN18 (DIP, 18-Pin, Row Spacing 7.62 mm, Pitch 2.54 mm)
pins: 1 ~{CS} (in), 2 ~{RD} (in), 3 TP (MODE) (in), 4 ~{BUSY} (out), 5 CLK (in), 6 D7(MSB) (hiz), 7 D6 (hiz), 8 D5 (hiz), 9 DGND (power), 10 D4 (hiz), 11 D3 (hiz), 12 D2 (hiz), 13 D1 (hiz), 14 D0(LSB) (hiz), 15 AGND (power), 16 AIN (in), 17 REF (in), 18 VDD (power)

## MX7575KP
designator U?
CMOS, µP-Compatible, 5µs 8-Bit ADCs
footprint PLCC20_N (Leaded Chip Carrier, 20-Leads, Body 9x9mm, Pitch 1.27mm, IPC Medium Density)
footprint PLCC20_L (Leaded Chip Carrier, 20-Leads, Body 9x9mm, Pitch 1.27mm, IPC High Density)
footprint PLCC20_M (Leaded Chip Carrier, 20-Leads, Body 9x9mm, Pitch 1.27mm, IPC Low Density)
3D model MX7575-PLCC20 (20-Pin Leaded Chip Carrier 1.27 mm Pitch)
pins: 1 NC, 2 ~{CS} (in), 3 ~{RD} (in), 4 TP (MODE) (in), 5 ~{BUSY} (out), 6 CLK (in), 7 D7(MSB) (hiz), 8 D6 (hiz), 9 D5 (hiz), 10 DGND (power), 11 NC, 12 D4 (hiz), 13 D3 (hiz), 14 D2 (hiz), 15 D1 (hiz), 16 D0(LSB) (hiz), 17 AGND (power), 18 AIN (in), 19 REF (in), 20 VDD (power)

## MX7575SQ
designator U?
CMOS, µP-Compatible, 5µs 8-Bit ADCs
footprint JN18 (DIP, 18-Leads, Row Spacing 7.62mm, Pitch 2.54mm, Body 24.13x6.73mm)
3D model JN18 (DIP, 18-Pin, Row Spacing 7.62 mm, Pitch 2.54 mm)
pins: 1 ~{CS} (in), 2 ~{RD} (in), 3 TP (MODE) (in), 4 ~{BUSY} (out), 5 CLK (in), 6 D7(MSB) (hiz), 7 D6 (hiz), 8 D5 (hiz), 9 DGND (power), 10 D4 (hiz), 11 D3 (hiz), 12 D2 (hiz), 13 D1 (hiz), 14 D0(LSB) (hiz), 15 AGND (power), 16 AIN (in), 17 REF (in), 18 VDD (power)

## MX7575TQ
designator U?
CMOS, µP-Compatible, 5µs 8-Bit ADCs
footprint JN18 (DIP, 18-Leads, Row Spacing 7.62mm, Pitch 2.54mm, Body 24.13x6.73mm)
3D model JN18 (DIP, 18-Pin, Row Spacing 7.62 mm, Pitch 2.54 mm)
pins: 1 ~{CS} (in), 2 ~{RD} (in), 3 TP (MODE) (in), 4 ~{BUSY} (out), 5 CLK (in), 6 D7(MSB) (hiz), 7 D6 (hiz), 8 D5 (hiz), 9 DGND (power), 10 D4 (hiz), 11 D3 (hiz), 12 D2 (hiz), 13 D1 (hiz), 14 D0(LSB) (hiz), 15 AGND (power), 16 AIN (in), 17 REF (in), 18 VDD (power)

## MX7576AQ
designator U?
CMOS, µP-Compatible, 10µs 8-Bit ADCs
footprint JN18 (DIP, 18-Leads, Row Spacing 7.62mm, Pitch 2.54mm, Body 24.13x6.73mm)
3D model JN18 (DIP, 18-Pin, Row Spacing 7.62 mm, Pitch 2.54 mm)
pins: 1 ~{CS} (in), 2 ~{RD} (in), 3 TP (MODE) (in), 4 ~{BUSY} (out), 5 CLK (in), 6 D7(MSB) (hiz), 7 D6 (hiz), 8 D5 (hiz), 9 DGND (power), 10 D4 (hiz), 11 D3 (hiz), 12 D2 (hiz), 13 D1 (hiz), 14 D0(LSB) (hiz), 15 AGND (power), 16 AIN (in), 17 REF (in), 18 VDD (power)

## MX7576BQ
designator U?
CMOS, µP-Compatible, 10µs 8-Bit ADCs
footprint JN18 (DIP, 18-Leads, Row Spacing 7.62mm, Pitch 2.54mm, Body 24.13x6.73mm)
3D model JN18 (DIP, 18-Pin, Row Spacing 7.62 mm, Pitch 2.54 mm)
pins: 1 ~{CS} (in), 2 ~{RD} (in), 3 TP (MODE) (in), 4 ~{BUSY} (out), 5 CLK (in), 6 D7(MSB) (hiz), 7 D6 (hiz), 8 D5 (hiz), 9 DGND (power), 10 D4 (hiz), 11 D3 (hiz), 12 D2 (hiz), 13 D1 (hiz), 14 D0(LSB) (hiz), 15 AGND (power), 16 AIN (in), 17 REF (in), 18 VDD (power)

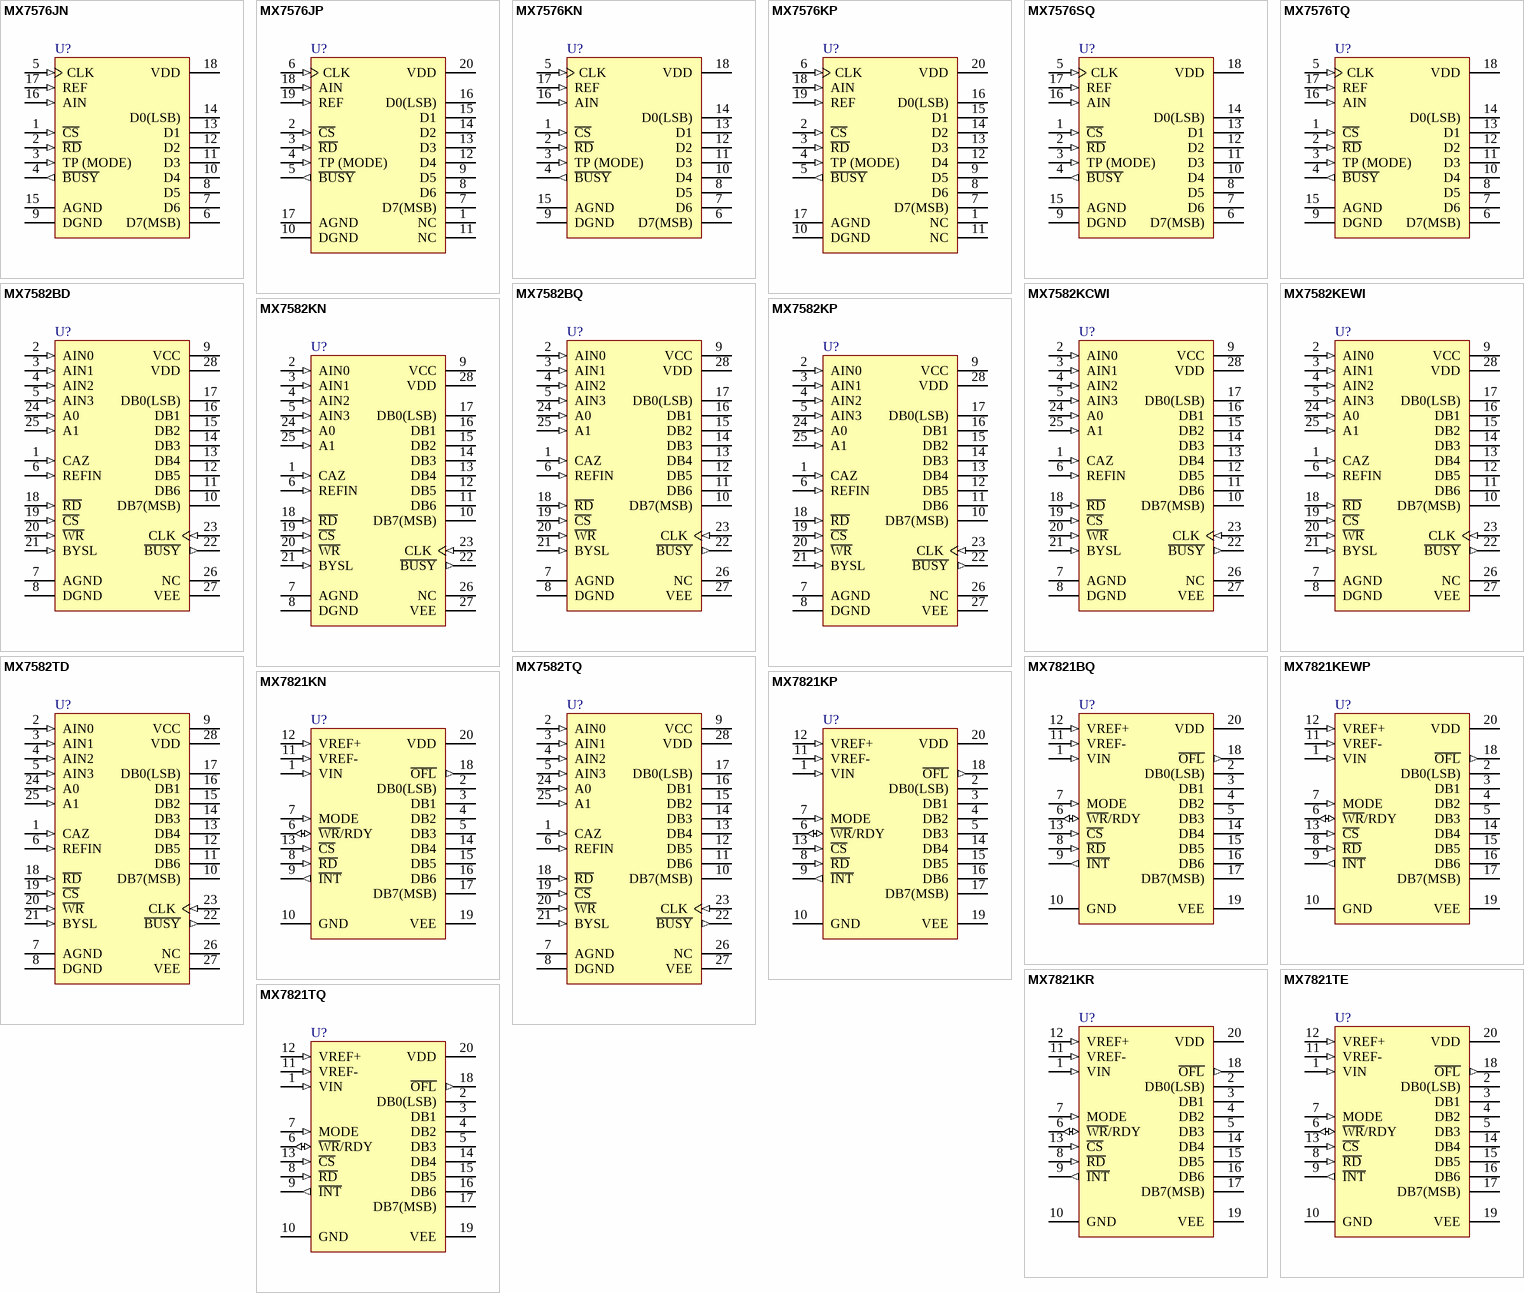
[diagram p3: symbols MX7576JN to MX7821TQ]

## MX7576JN
designator U?
CMOS, µP-Compatible, 10µs 8-Bit ADCs
footprint PN18A (DIP, 18-Leads, Row Spacing 7.62mm, Pitch 2.54mm, Body 22.86x6.99mm)
3D model PN18 (DIP, 18-Pin, Row Spacing 7.62 mm, Pitch 2.54 mm)
pins: 1 ~{CS} (in), 2 ~{RD} (in), 3 TP (MODE) (in), 4 ~{BUSY} (out), 5 CLK (in), 6 D7(MSB) (hiz), 7 D6 (hiz), 8 D5 (hiz), 9 DGND (power), 10 D4 (hiz), 11 D3 (hiz), 12 D2 (hiz), 13 D1 (hiz), 14 D0(LSB) (hiz), 15 AGND (power), 16 AIN (in), 17 REF (in), 18 VDD (power)

## MX7576JP
designator U?
CMOS, µP-Compatible, 10µs 8-Bit ADCs
footprint PLCC20_N (Leaded Chip Carrier, 20-Leads, Body 9x9mm, Pitch 1.27mm, IPC Medium Density)
footprint PLCC20_L (Leaded Chip Carrier, 20-Leads, Body 9x9mm, Pitch 1.27mm, IPC High Density)
footprint PLCC20_M (Leaded Chip Carrier, 20-Leads, Body 9x9mm, Pitch 1.27mm, IPC Low Density)
3D model MX7576-PLCC20 (20-Pin Leaded Chip Carrier 1.27 mm Pitch)
pins: 1 NC, 2 ~{CS} (in), 3 ~{RD} (in), 4 TP (MODE) (in), 5 ~{BUSY} (out), 6 CLK (in), 7 D7(MSB) (hiz), 8 D6 (hiz), 9 D5 (hiz), 10 DGND (power), 11 NC, 12 D4 (hiz), 13 D3 (hiz), 14 D2 (hiz), 15 D1 (hiz), 16 D0(LSB) (hiz), 17 AGND (power), 18 AIN (in), 19 REF (in), 20 VDD (power)

## MX7576KN
designator U?
CMOS, µP-Compatible, 10µs 8-Bit ADCs
footprint PN18A (DIP, 18-Leads, Row Spacing 7.62mm, Pitch 2.54mm, Body 22.86x6.99mm)
3D model PN18 (DIP, 18-Pin, Row Spacing 7.62 mm, Pitch 2.54 mm)
pins: 1 ~{CS} (in), 2 ~{RD} (in), 3 TP (MODE) (in), 4 ~{BUSY} (out), 5 CLK (in), 6 D7(MSB) (hiz), 7 D6 (hiz), 8 D5 (hiz), 9 DGND (power), 10 D4 (hiz), 11 D3 (hiz), 12 D2 (hiz), 13 D1 (hiz), 14 D0(LSB) (hiz), 15 AGND (power), 16 AIN (in), 17 REF (in), 18 VDD (power)

## MX7576KP
designator U?
CMOS, µP-Compatible, 10µs 8-Bit ADCs
footprint PLCC20_N (Leaded Chip Carrier, 20-Leads, Body 9x9mm, Pitch 1.27mm, IPC Medium Density)
footprint PLCC20_L (Leaded Chip Carrier, 20-Leads, Body 9x9mm, Pitch 1.27mm, IPC High Density)
footprint PLCC20_M (Leaded Chip Carrier, 20-Leads, Body 9x9mm, Pitch 1.27mm, IPC Low Density)
3D model MX7576-PLCC20 (20-Pin Leaded Chip Carrier 1.27 mm Pitch)
pins: 1 NC, 2 ~{CS} (in), 3 ~{RD} (in), 4 TP (MODE) (in), 5 ~{BUSY} (out), 6 CLK (in), 7 D7(MSB) (hiz), 8 D6 (hiz), 9 D5 (hiz), 10 DGND (power), 11 NC, 12 D4 (hiz), 13 D3 (hiz), 14 D2 (hiz), 15 D1 (hiz), 16 D0(LSB) (hiz), 17 AGND (power), 18 AIN (in), 19 REF (in), 20 VDD (power)

## MX7576SQ
designator U?
CMOS, µP-Compatible, 10µs 8-Bit ADCs
footprint JN18 (DIP, 18-Leads, Row Spacing 7.62mm, Pitch 2.54mm, Body 24.13x6.73mm)
3D model JN18 (DIP, 18-Pin, Row Spacing 7.62 mm, Pitch 2.54 mm)
pins: 1 ~{CS} (in), 2 ~{RD} (in), 3 TP (MODE) (in), 4 ~{BUSY} (out), 5 CLK (in), 6 D7(MSB) (hiz), 7 D6 (hiz), 8 D5 (hiz), 9 DGND (power), 10 D4 (hiz), 11 D3 (hiz), 12 D2 (hiz), 13 D1 (hiz), 14 D0(LSB) (hiz), 15 AGND (power), 16 AIN (in), 17 REF (in), 18 VDD (power)

## MX7576TQ
designator U?
CMOS, µP-Compatible, 10µs 8-Bit ADCs
footprint JN18 (DIP, 18-Leads, Row Spacing 7.62mm, Pitch 2.54mm, Body 24.13x6.73mm)
3D model JN18 (DIP, 18-Pin, Row Spacing 7.62 mm, Pitch 2.54 mm)
pins: 1 ~{CS} (in), 2 ~{RD} (in), 3 TP (MODE) (in), 4 ~{BUSY} (out), 5 CLK (in), 6 D7(MSB) (hiz), 7 D6 (hiz), 8 D5 (hiz), 9 DGND (power), 10 D4 (hiz), 11 D3 (hiz), 12 D2 (hiz), 13 D1 (hiz), 14 D0(LSB) (hiz), 15 AGND (power), 16 AIN (in), 17 REF (in), 18 VDD (power)

## MX7582BD
designator U?
Calibrated 4-Channel 12-Bit ADC
footprint PI28 (DIP, 28-Leads, Row Spacing 15.24mm, Pitch 2.54mm, Body 36.83x13.98mm)
3D model JI28 (DIP, 28-Pin, Row Spacing 15.24 mm, Pitch 2.54 mm)
pins: 1 CAZ (in), 2 AIN0 (in), 3 AIN1 (in), 4 AIN2 (in), 5 AIN3 (in), 6 REFIN (in), 7 AGND (power), 8 DGND (power), 9 VCC (power), 10 DB7(MSB) (hiz), 11 DB6 (hiz), 12 DB5 (hiz), 13 DB4 (hiz), 14 DB3 (hiz), 15 DB2 (hiz), 16 DB1 (hiz), 17 DB0(LSB) (hiz), 18 ~{RD} (in), 19 ~{CS} (in), 20 ~{WR} (in), 21 BYSL (in), 22 ~{BUSY} (out), 23 CLK (in), 24 A0 (in), 25 A1 (in), 26 NC, 27 VEE (power), 28 VDD (power)

## MX7582BQ
designator U?
Calibrated 4-Channel 12-Bit ADC
footprint JI28A (DIP, 28-Leads, Row Spacing 15.24mm, Pitch 2.54mm, Body 37.15x14.1mm)
3D model JI28 (DIP, 28-Pin, Row Spacing 15.24 mm, Pitch 2.54 mm)
pins: 1 CAZ (in), 2 AIN0 (in), 3 AIN1 (in), 4 AIN2 (in), 5 AIN3 (in), 6 REFIN (in), 7 AGND (power), 8 DGND (power), 9 VCC (power), 10 DB7(MSB) (hiz), 11 DB6 (hiz), 12 DB5 (hiz), 13 DB4 (hiz), 14 DB3 (hiz), 15 DB2 (hiz), 16 DB1 (hiz), 17 DB0(LSB) (hiz), 18 ~{RD} (in), 19 ~{CS} (in), 20 ~{WR} (in), 21 BYSL (in), 22 ~{BUSY} (out), 23 CLK (in), 24 A0 (in), 25 A1 (in), 26 NC, 27 VEE (power), 28 VDD (power)

## MX7582KCWI
designator U?
Calibrated 4-Channel 12-Bit ADC
footprint WSO28_N (SOIC, 28-Leads, Body 17.9x7.5mm, Pitch 1.27mm, IPC Medium Density)
footprint WSO28_L (SOIC, 28-Leads, Body 17.9x7.5mm, Pitch 1.27mm, IPC High Density)
footprint WSO28_M (SOIC, 28-Leads, Body 17.9x7.5mm, Pitch 1.27mm, IPC Low Density)
3D model WSO28 (28-Pin Small Outline Integrated Circuit 1.27 mm Pitch)
pins: 1 CAZ (in), 2 AIN0 (in), 3 AIN1 (in), 4 AIN2 (in), 5 AIN3 (in), 6 REFIN (in), 7 AGND (power), 8 DGND (power), 9 VCC (power), 10 DB7(MSB) (hiz), 11 DB6 (hiz), 12 DB5 (hiz), 13 DB4 (hiz), 14 DB3 (hiz), 15 DB2 (hiz), 16 DB1 (hiz), 17 DB0(LSB) (hiz), 18 ~{RD} (in), 19 ~{CS} (in), 20 ~{WR} (in), 21 BYSL (in), 22 ~{BUSY} (out), 23 CLK (in), 24 A0 (in), 25 A1 (in), 26 NC, 27 VEE (power), 28 VDD (power)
